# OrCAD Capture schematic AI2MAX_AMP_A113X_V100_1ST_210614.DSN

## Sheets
1 03: POWER PART1: size A3; title: 03. POWER PART 1; rev: 0.31; note: AI2 MAX-AMP B/D
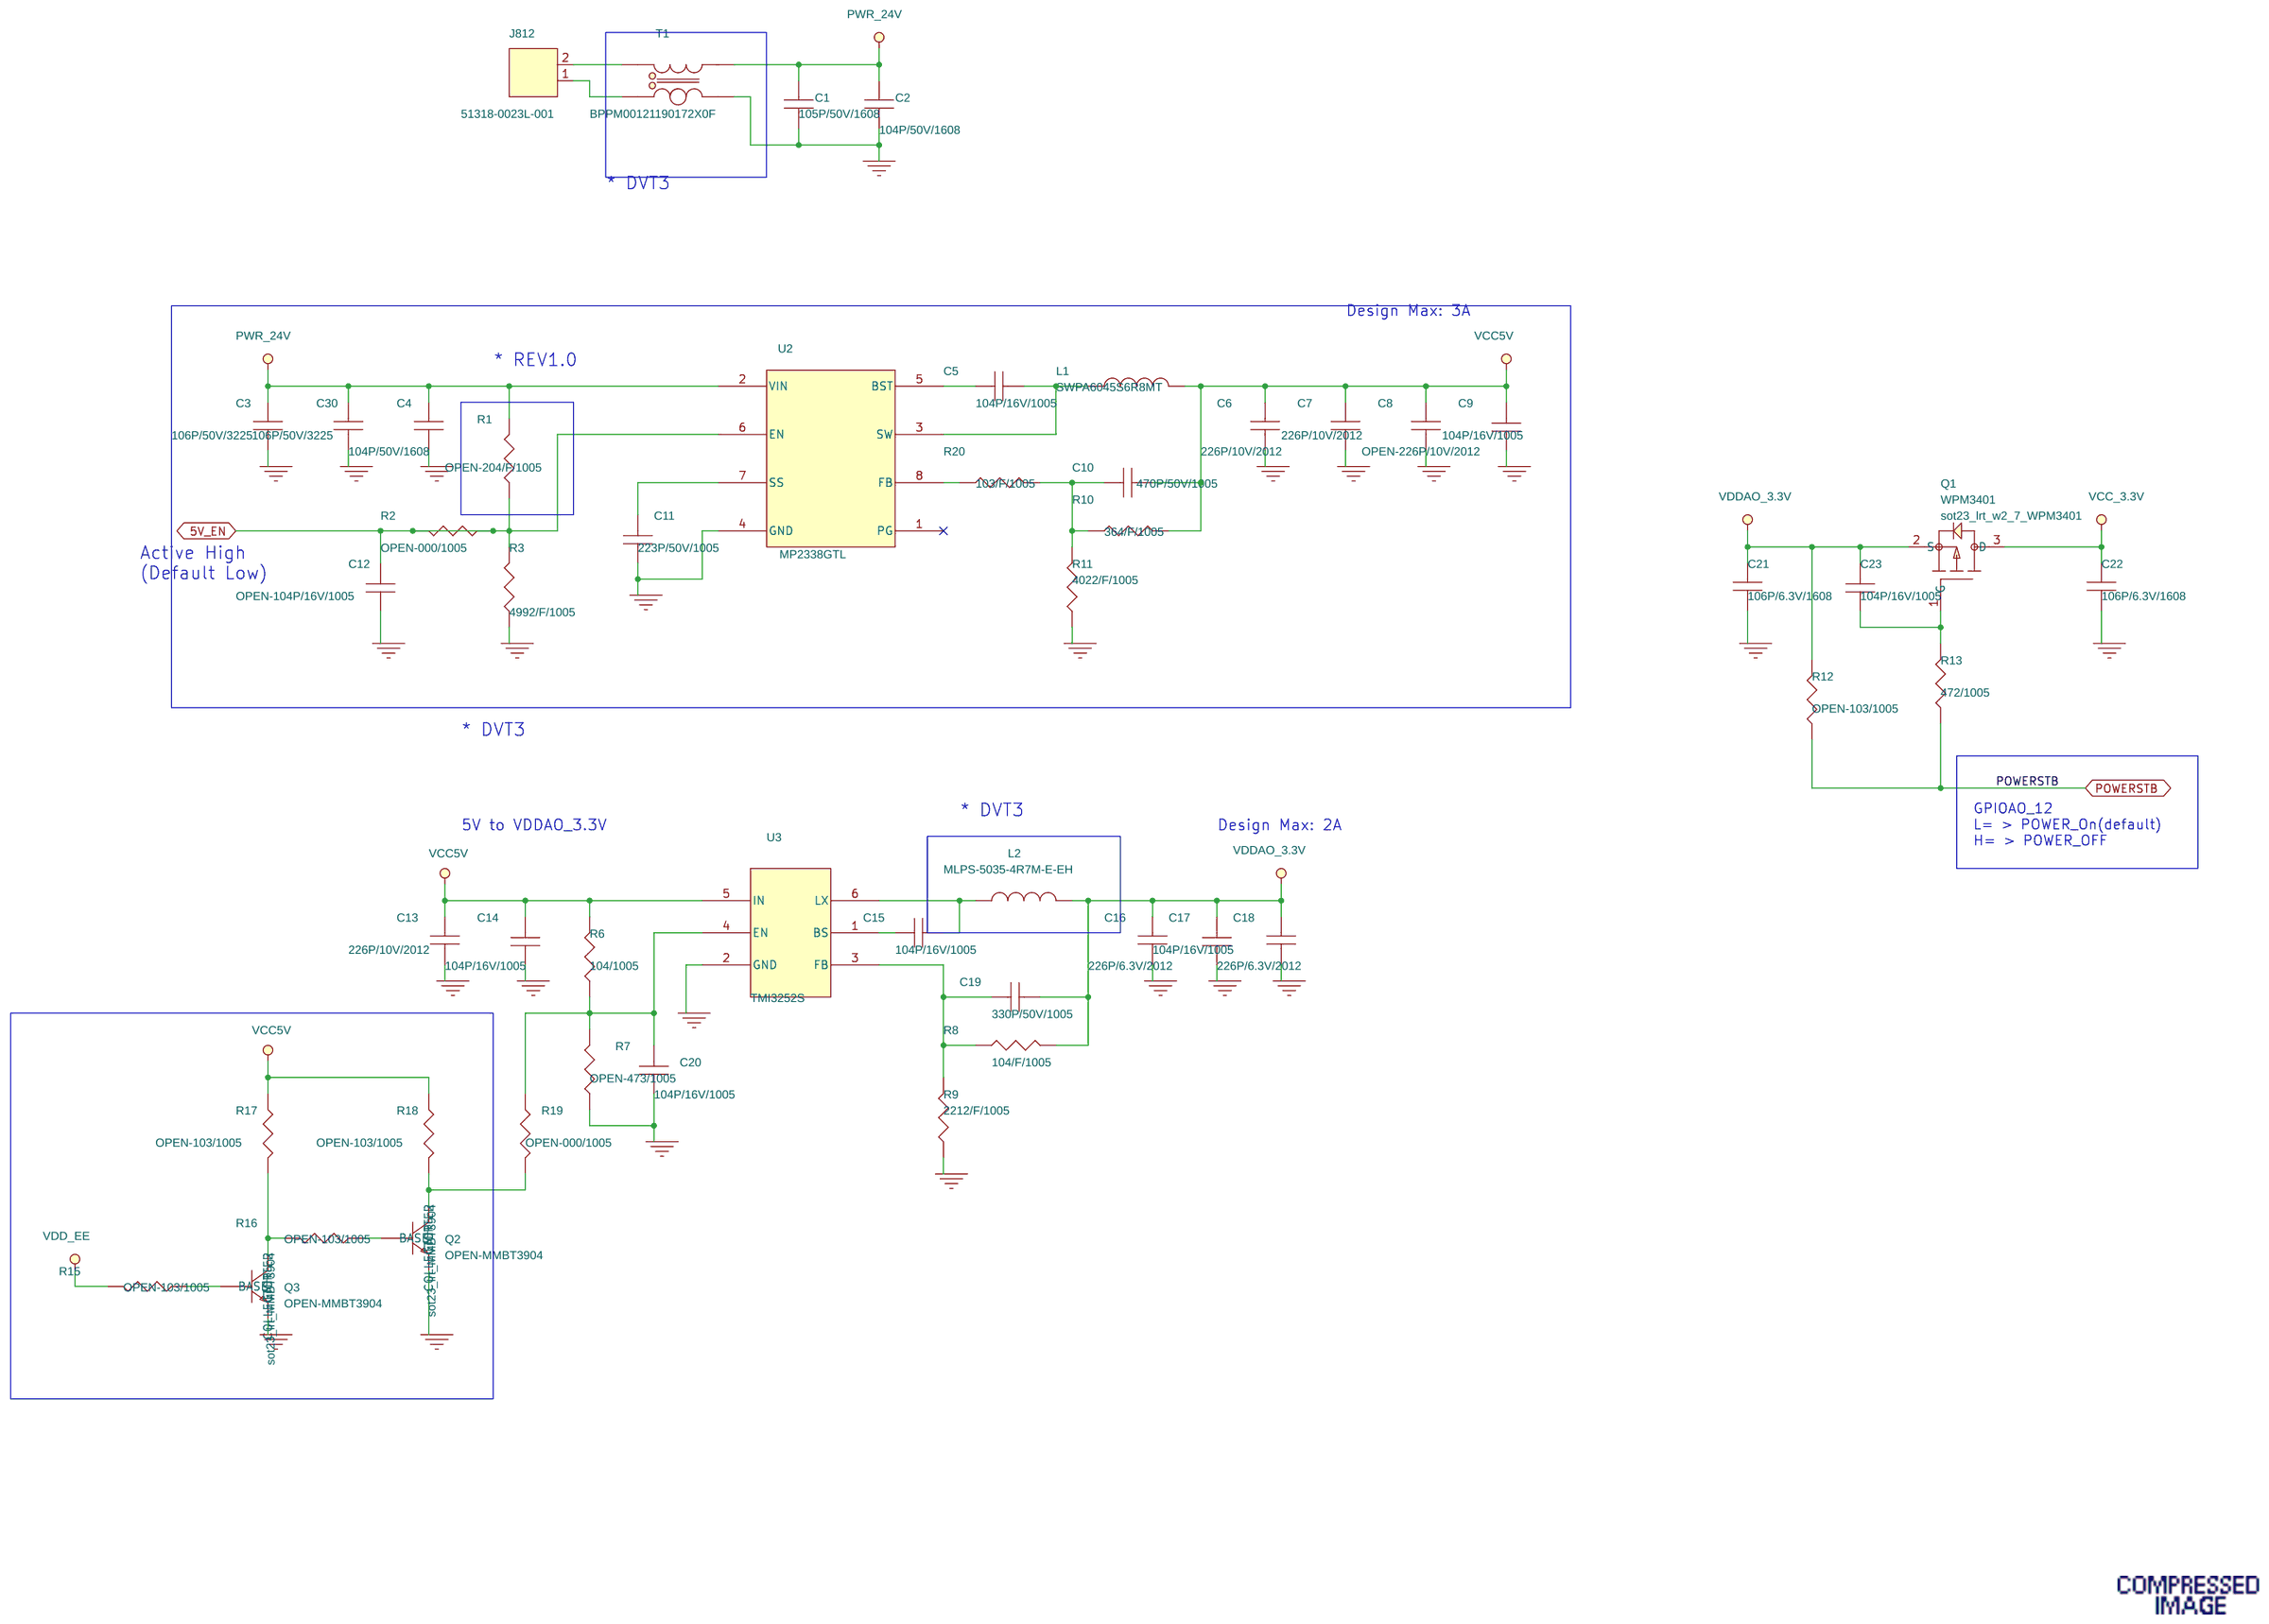
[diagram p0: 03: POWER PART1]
2 05: A113X_IO: size A3; title: 05. A113X_IO
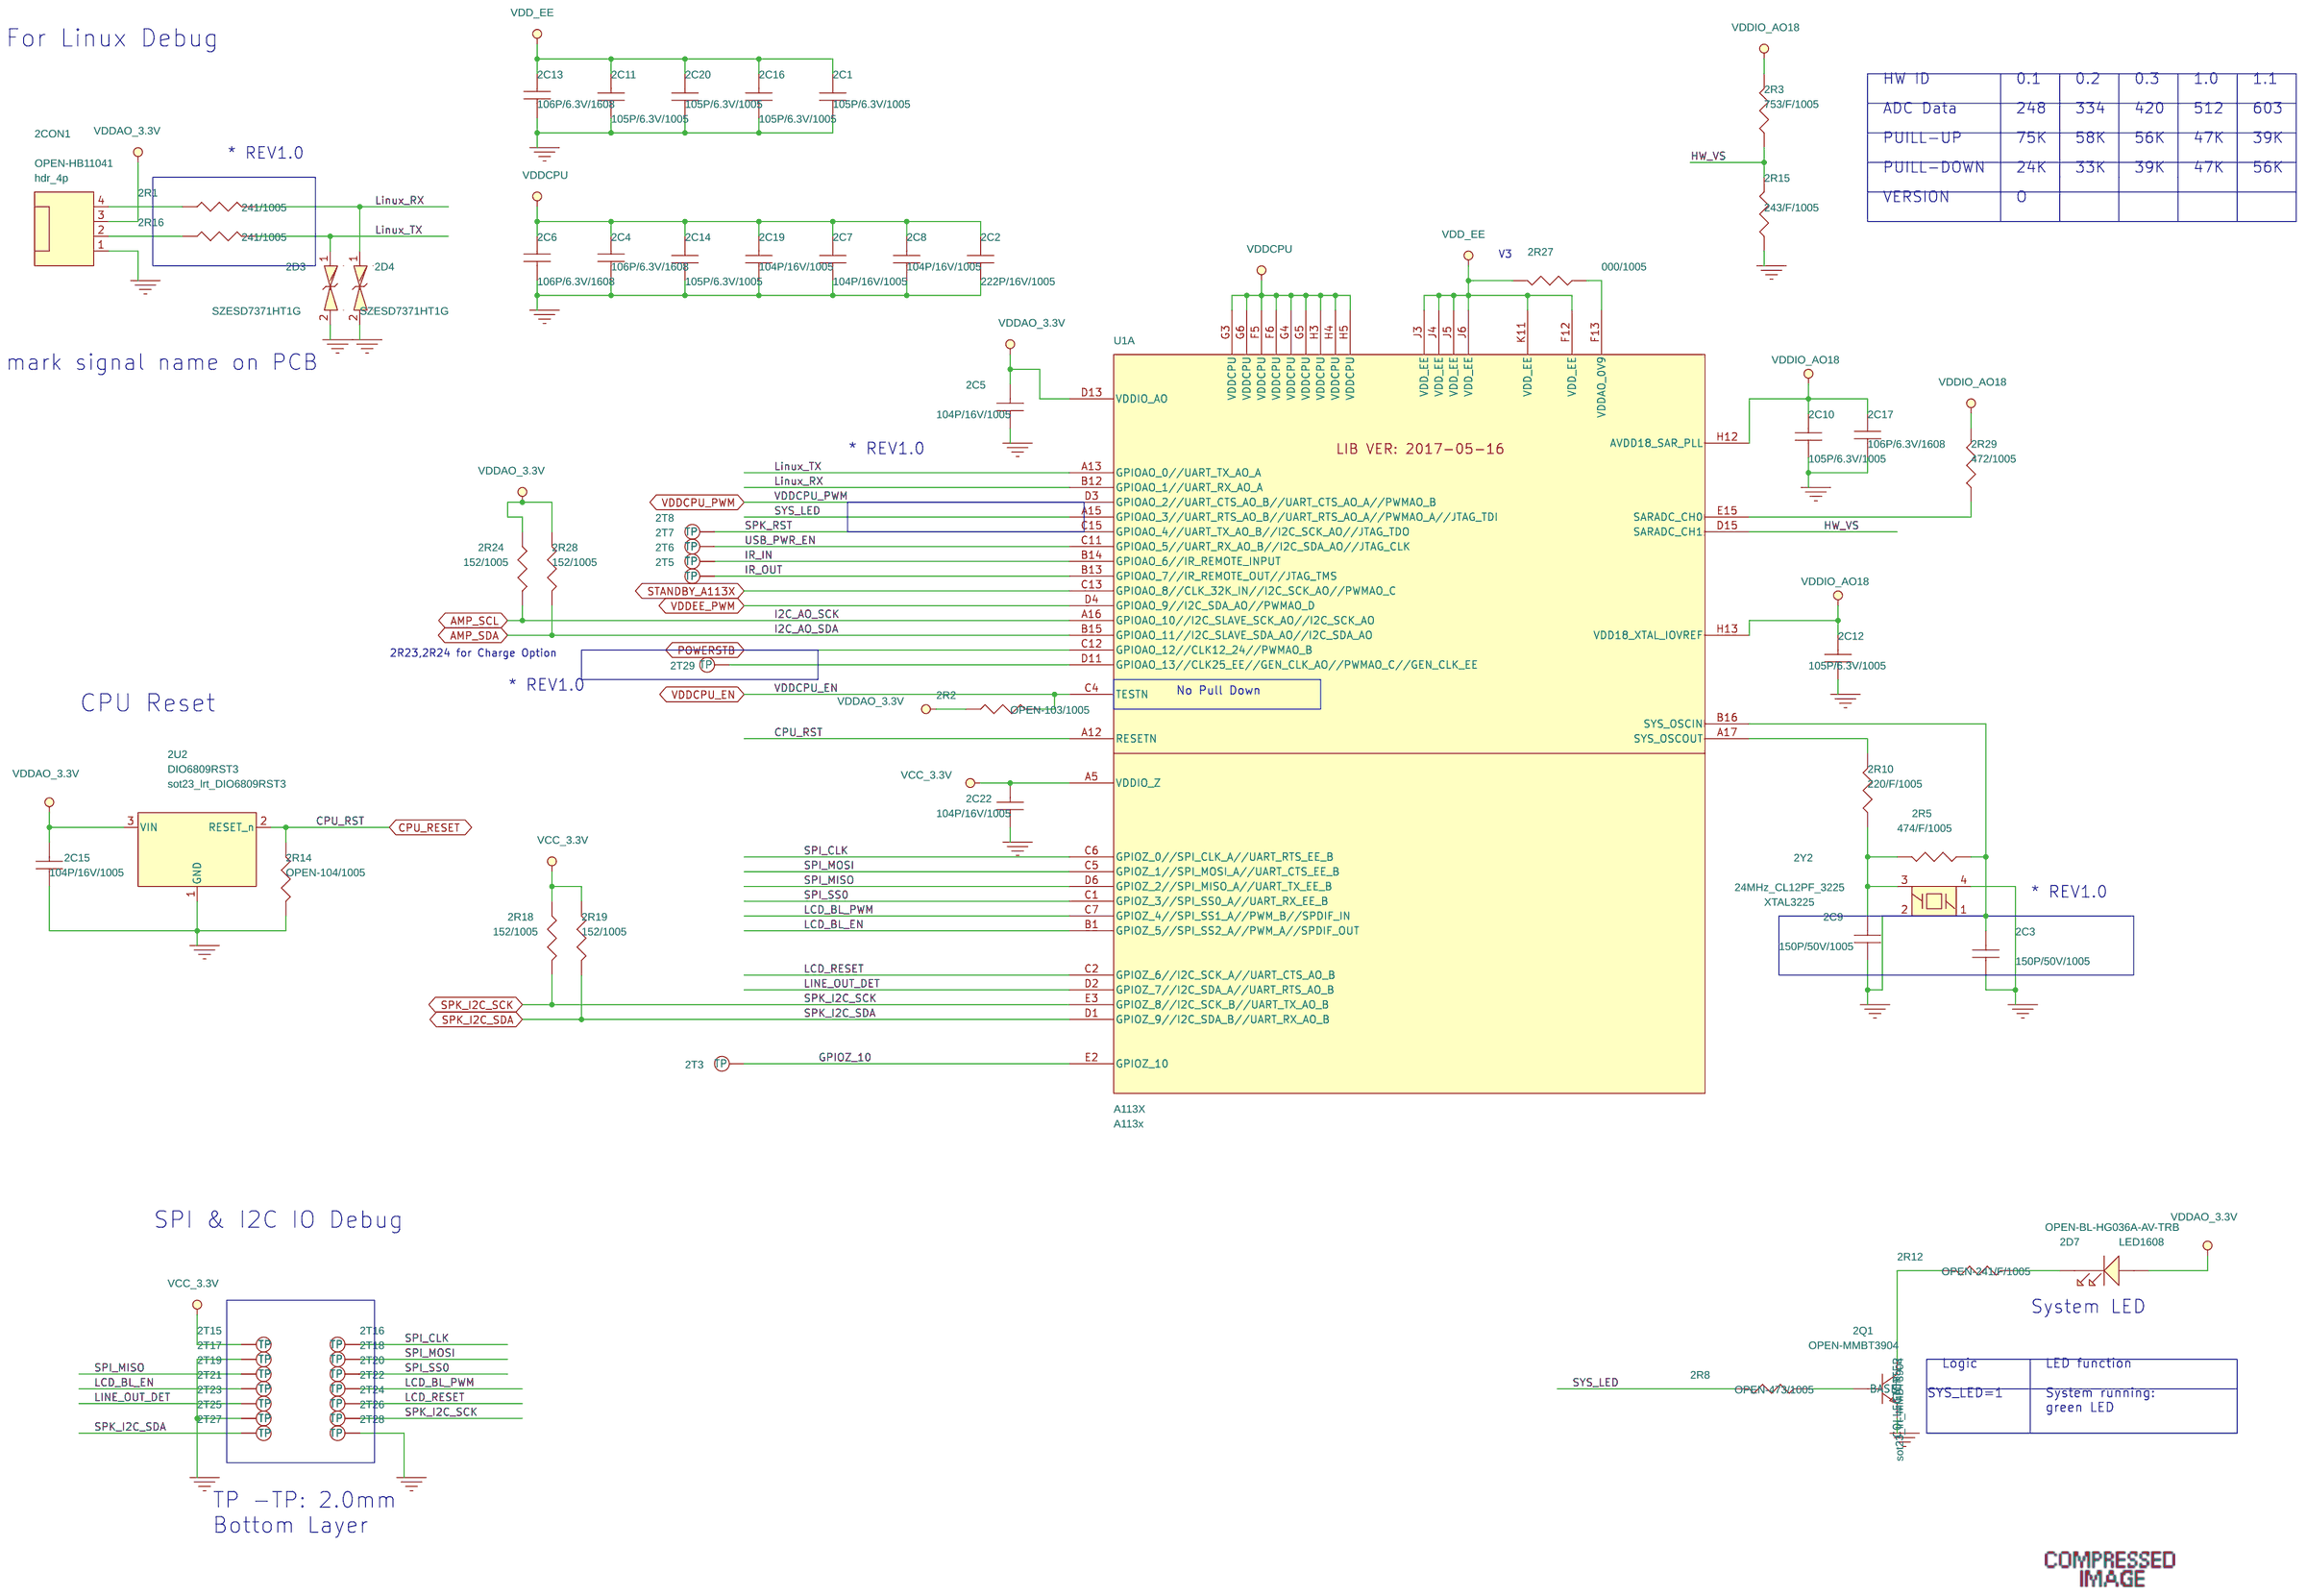
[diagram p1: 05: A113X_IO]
3 01: BLOCK: title: 01. BLOCK
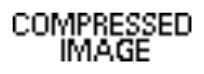
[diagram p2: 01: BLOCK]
4 02: POWER TREE: title: 02. POWER TREE
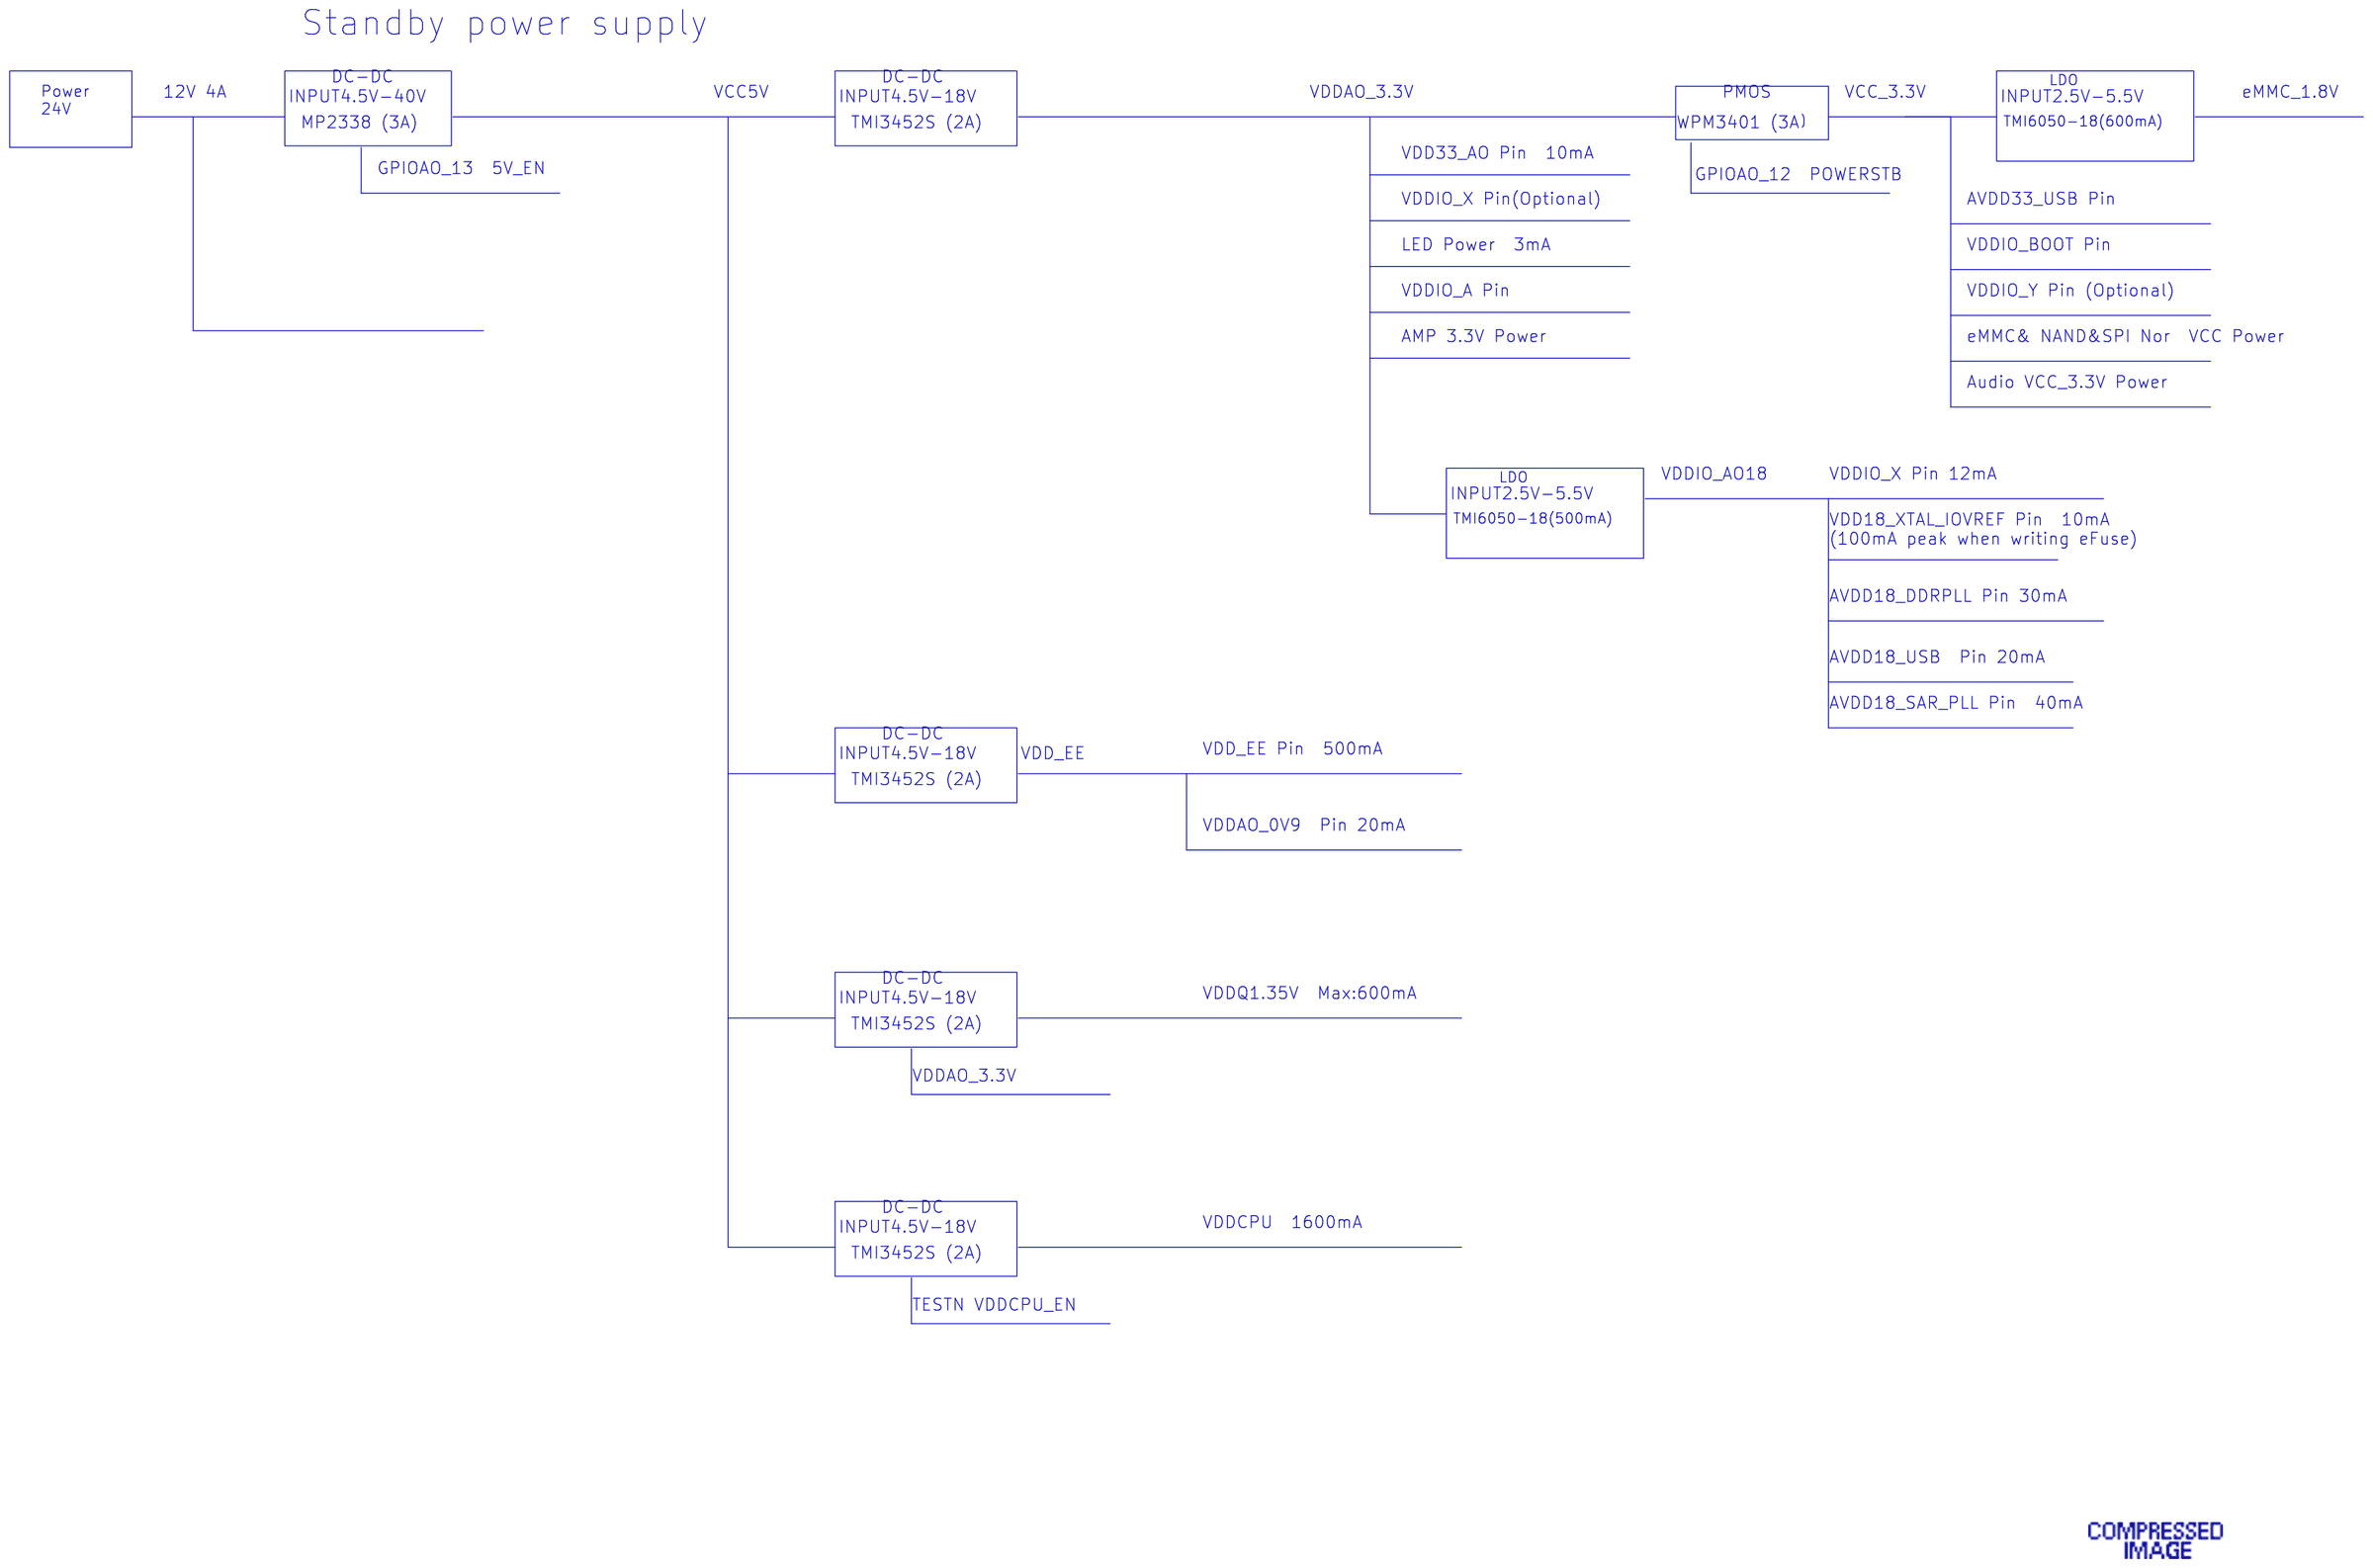
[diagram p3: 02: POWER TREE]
5 06: A113X_DDR3L: size A3; title: 06. A113X_DDR
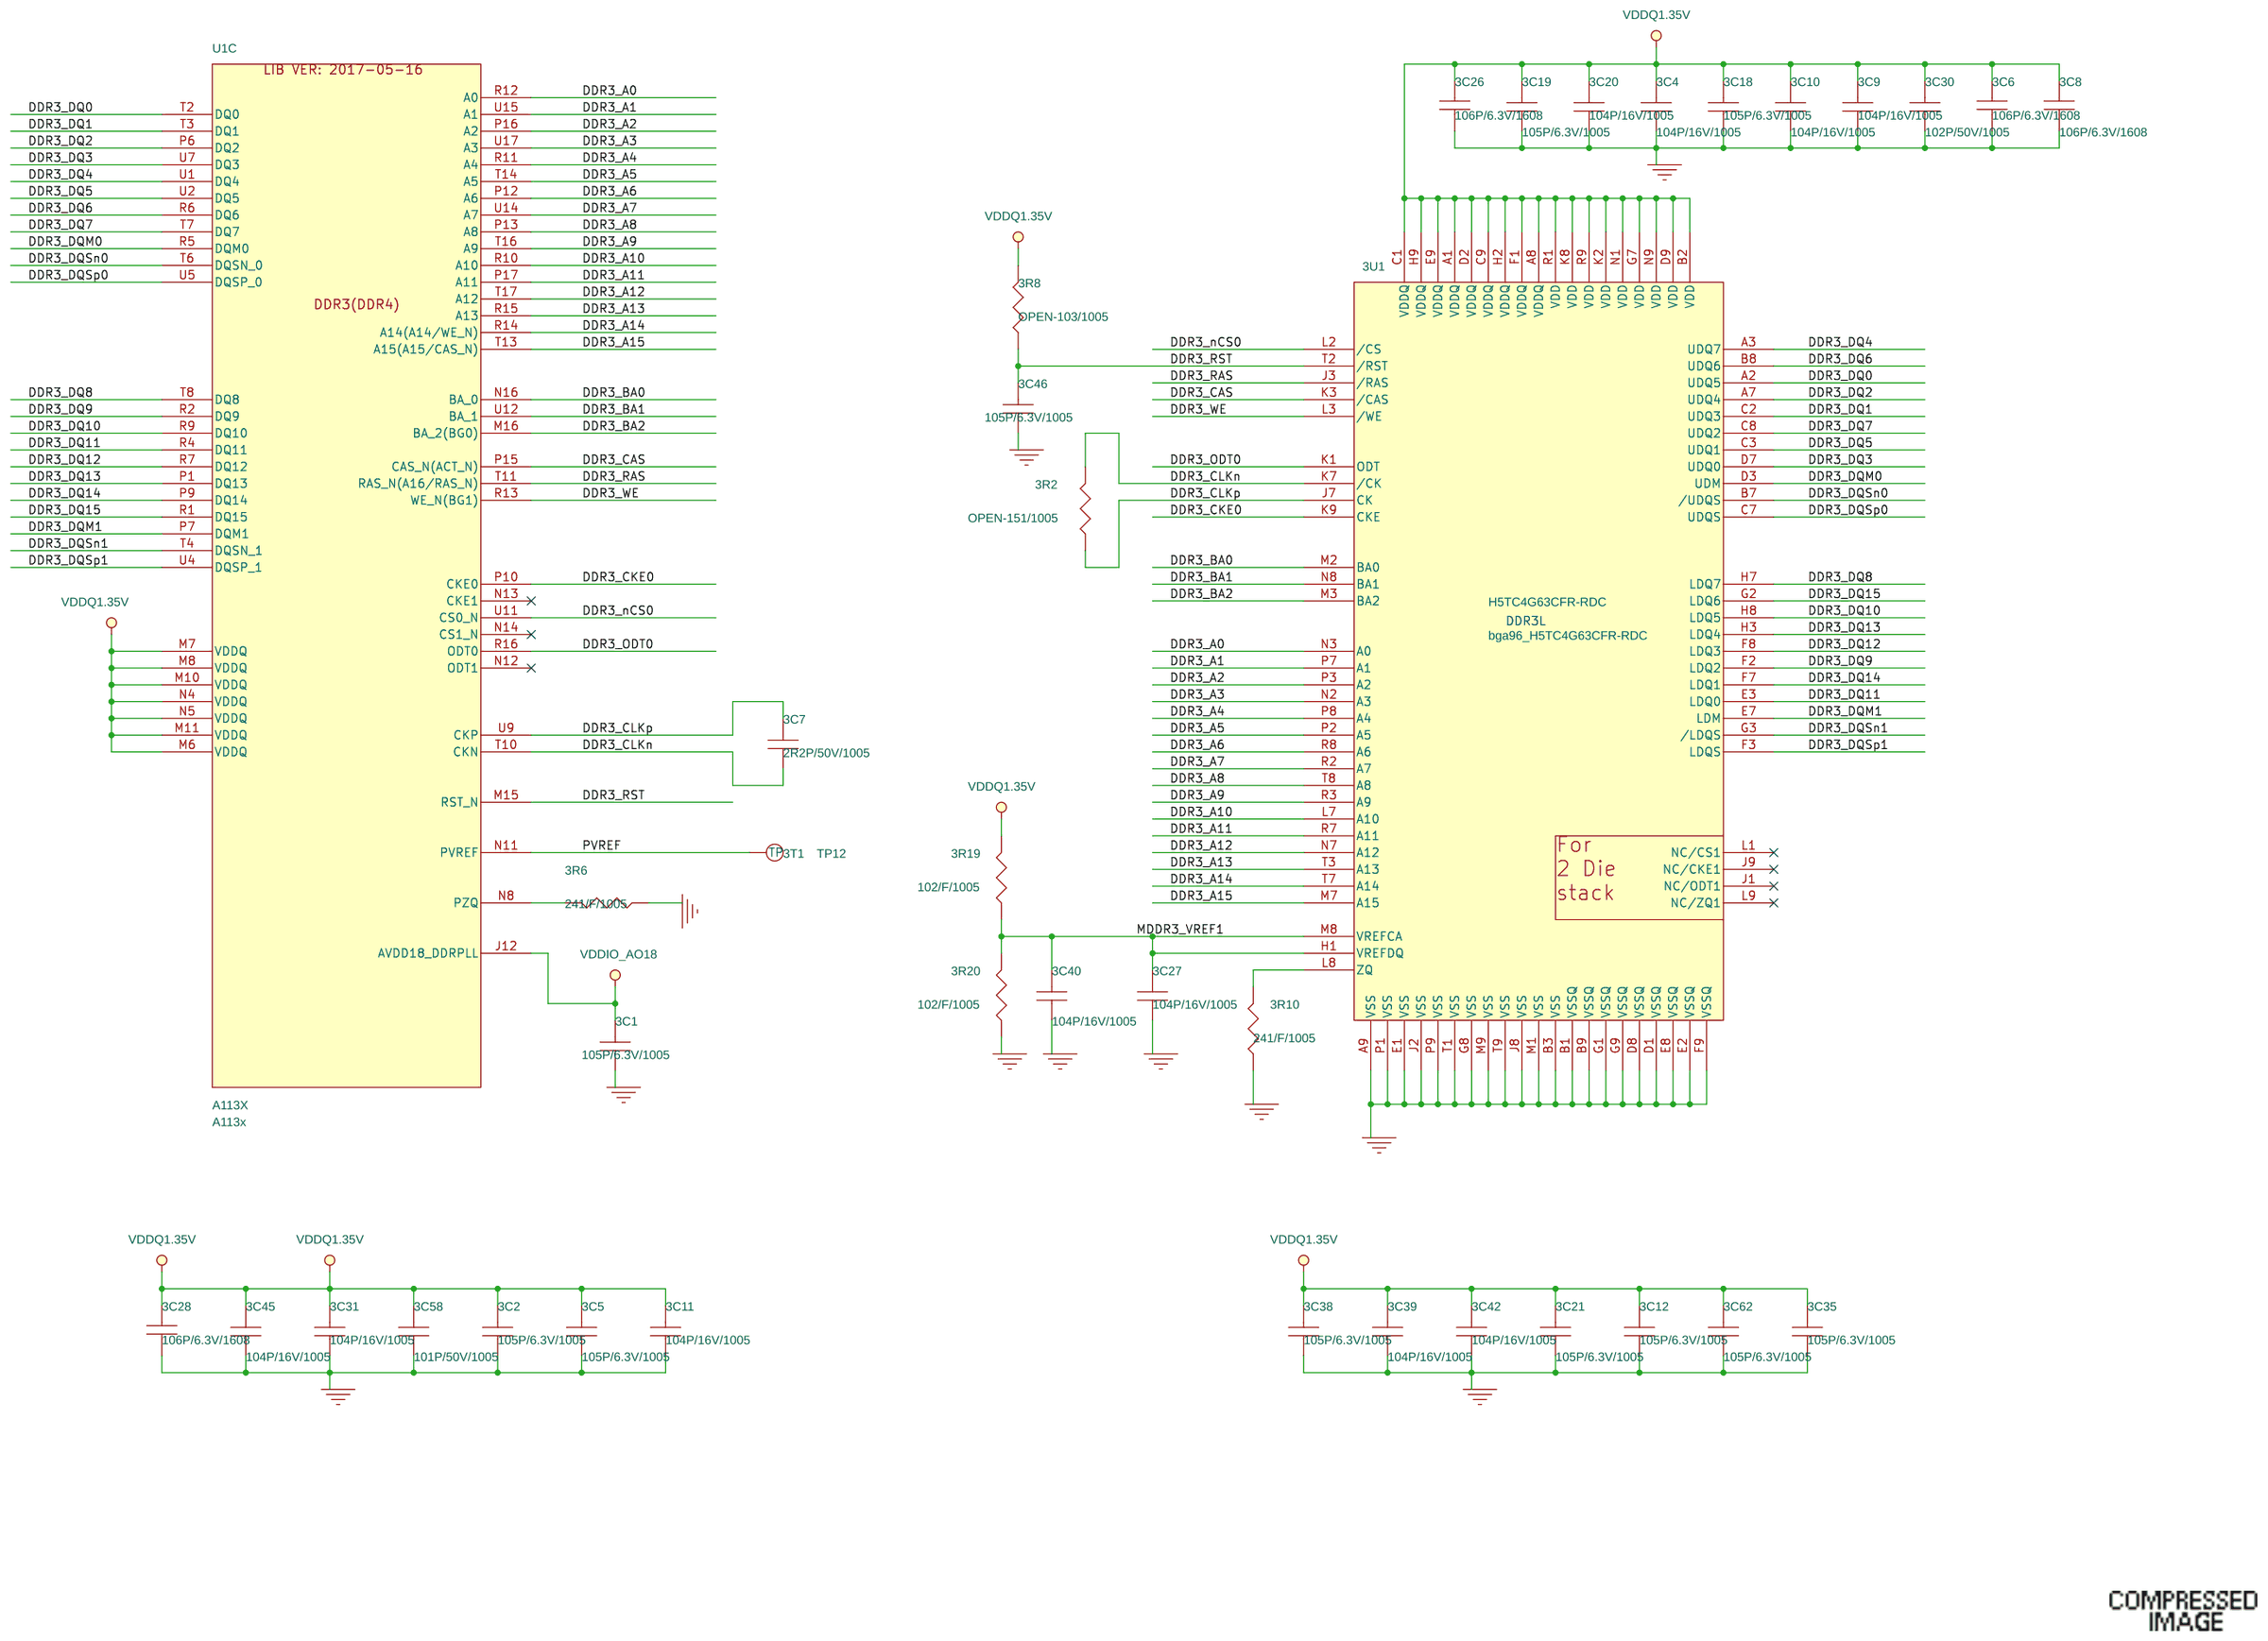
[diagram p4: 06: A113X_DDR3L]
6 04: POWER PART2: size A3; title: 04. POWER PART2; rev: 0.1
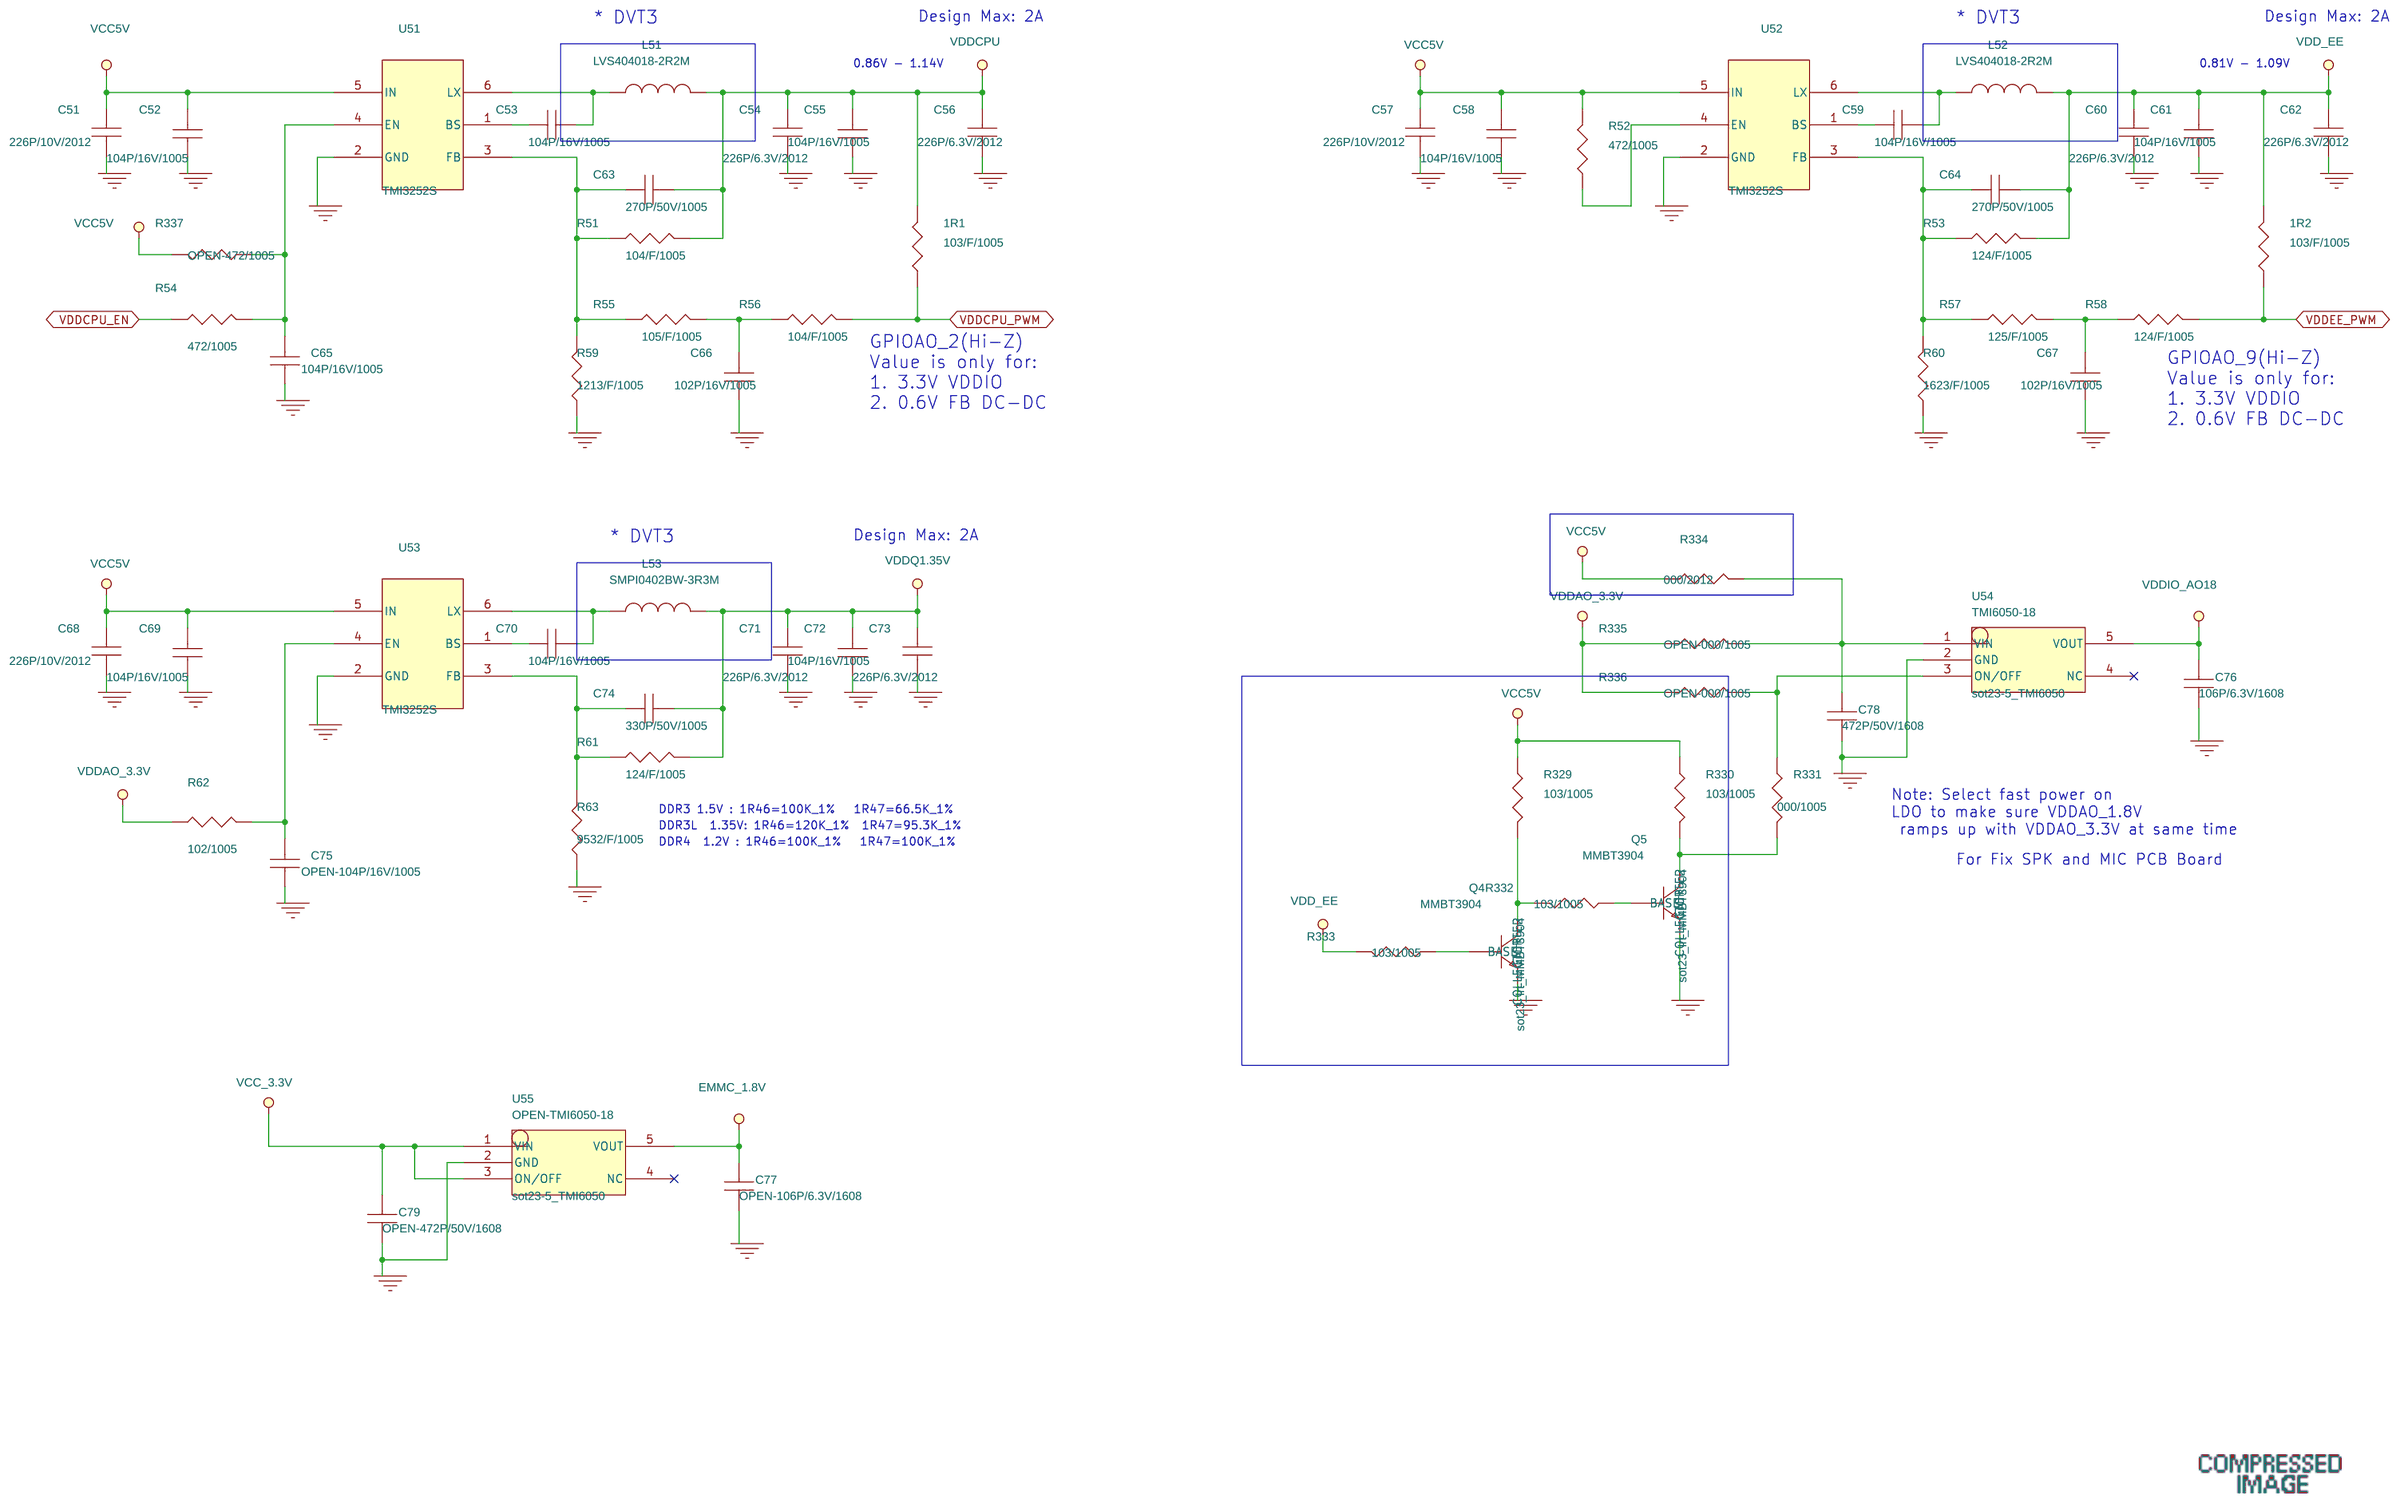
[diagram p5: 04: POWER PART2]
7 08: A113X_POWER: size A3; title: 08. A113X_POWER
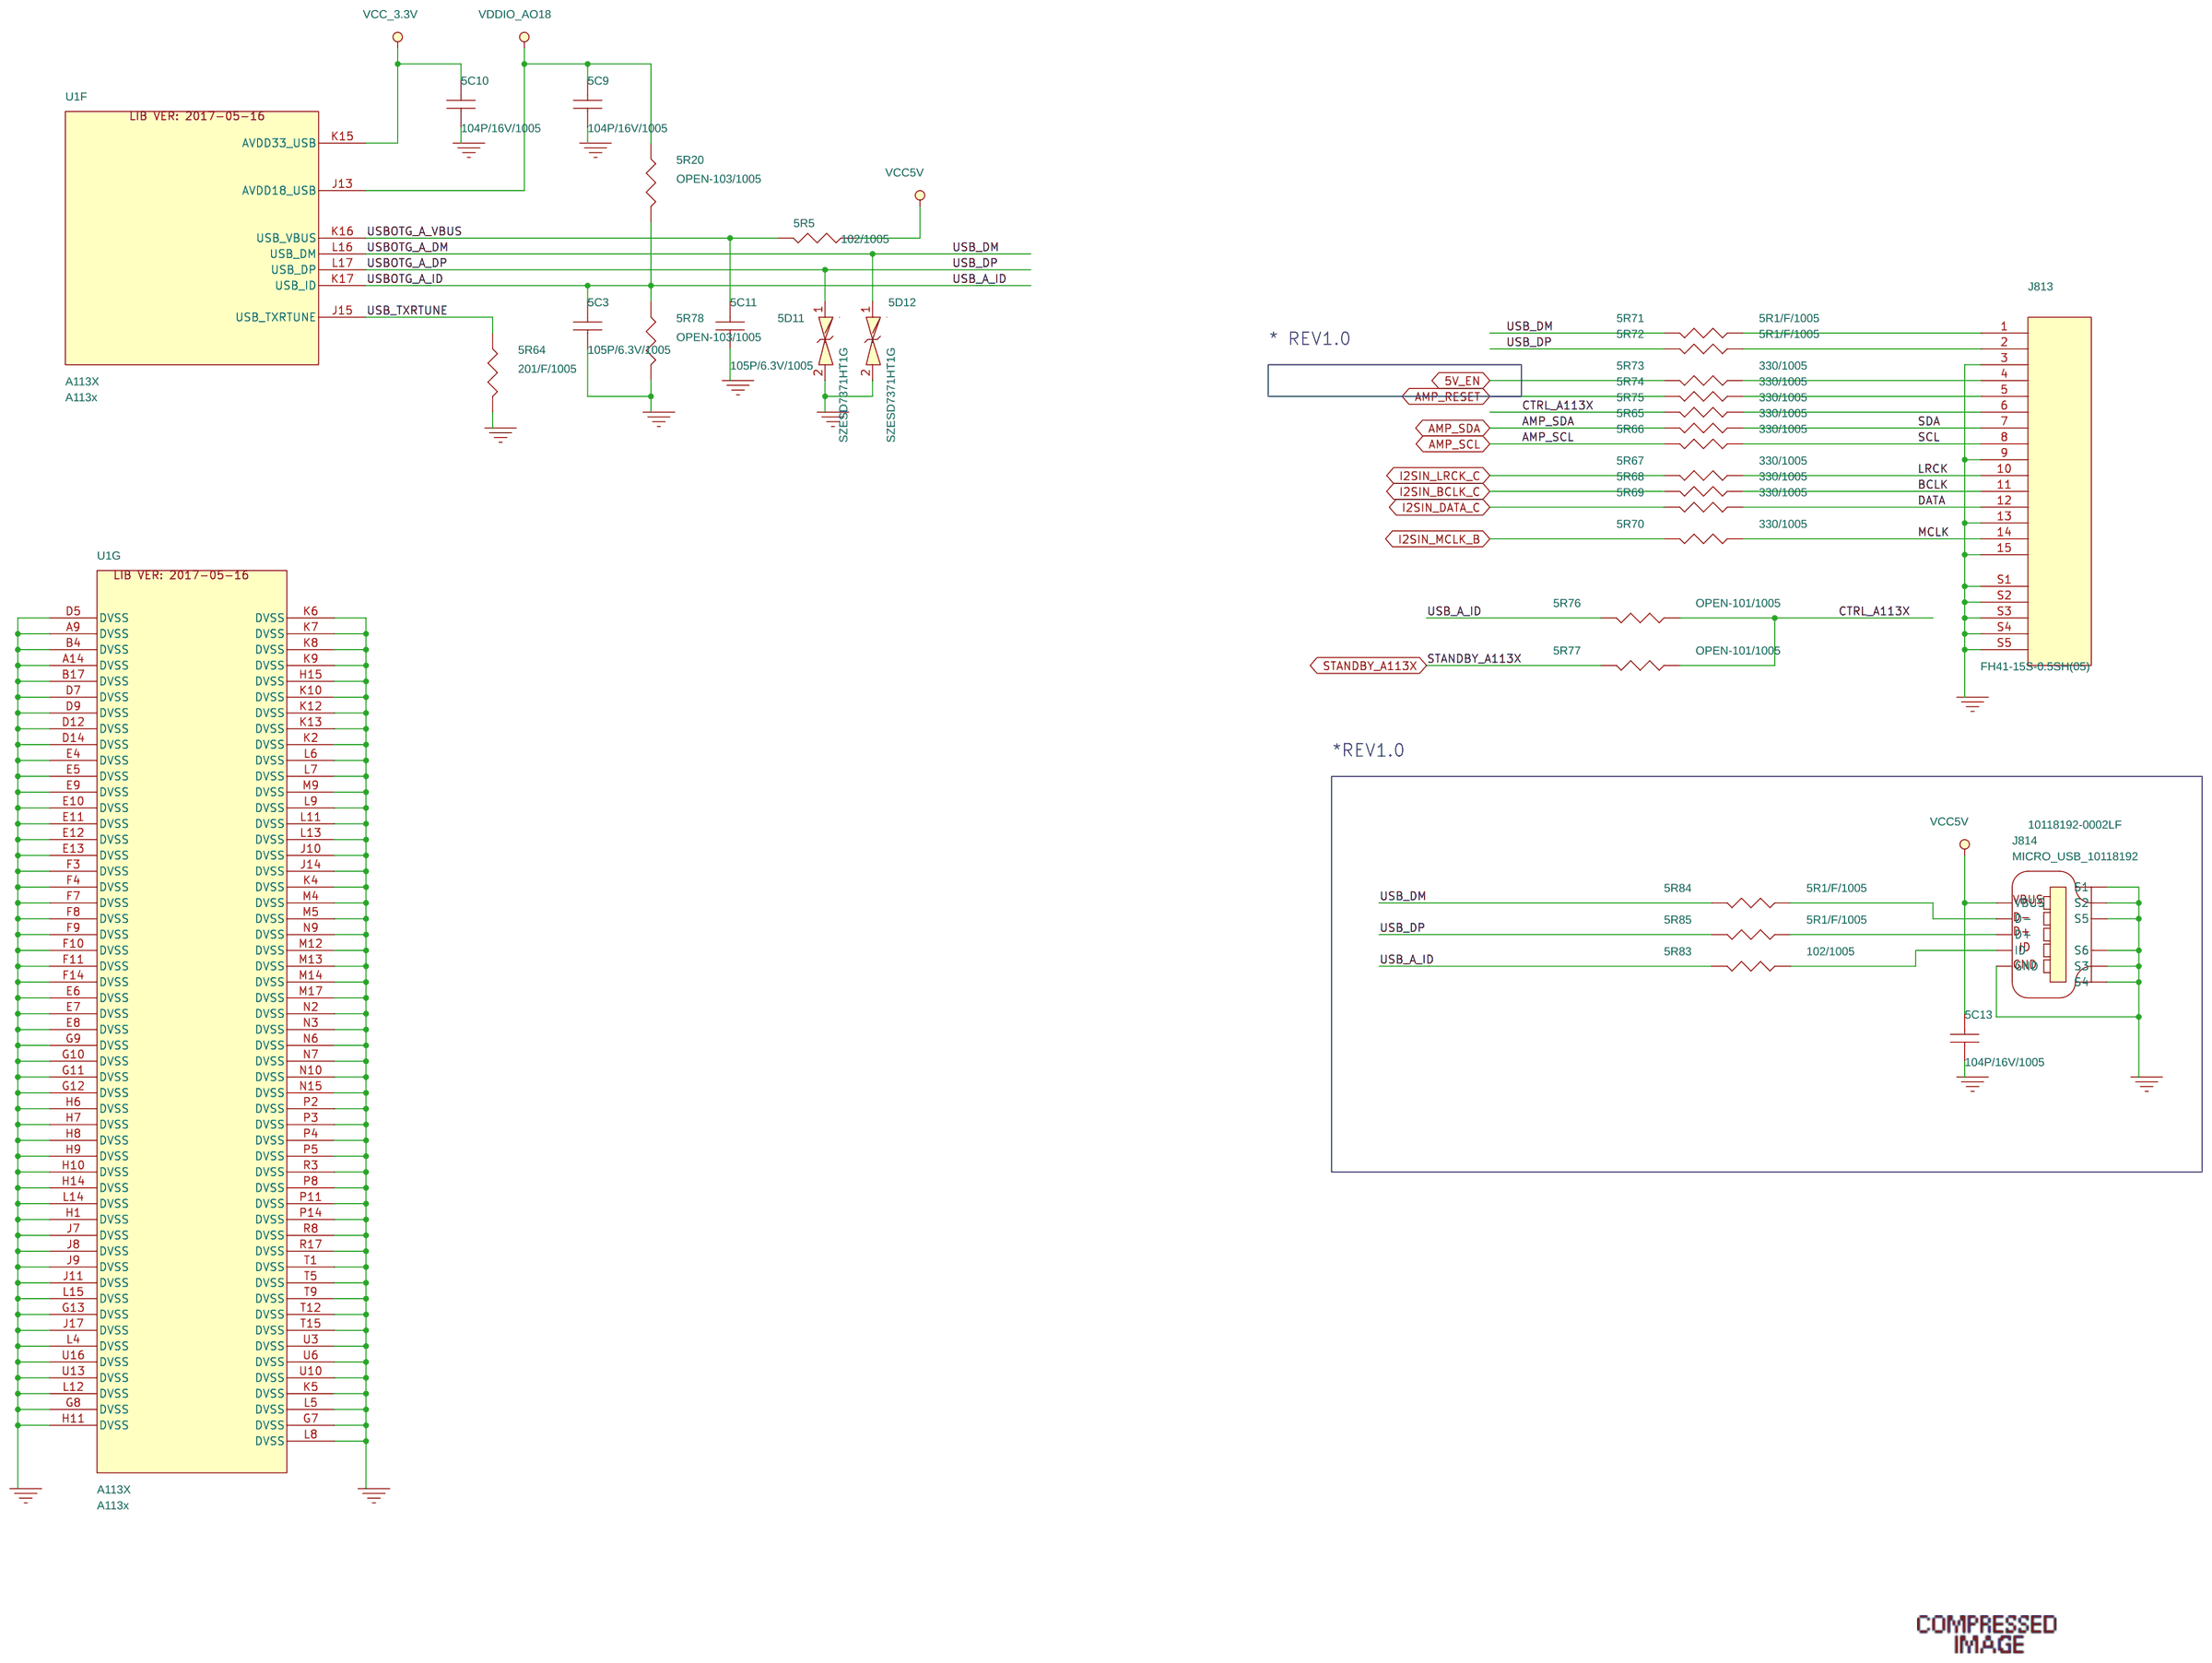
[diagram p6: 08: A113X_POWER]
8 07: A113X_FLASH: size A3; title: 07. A113X_FLASH
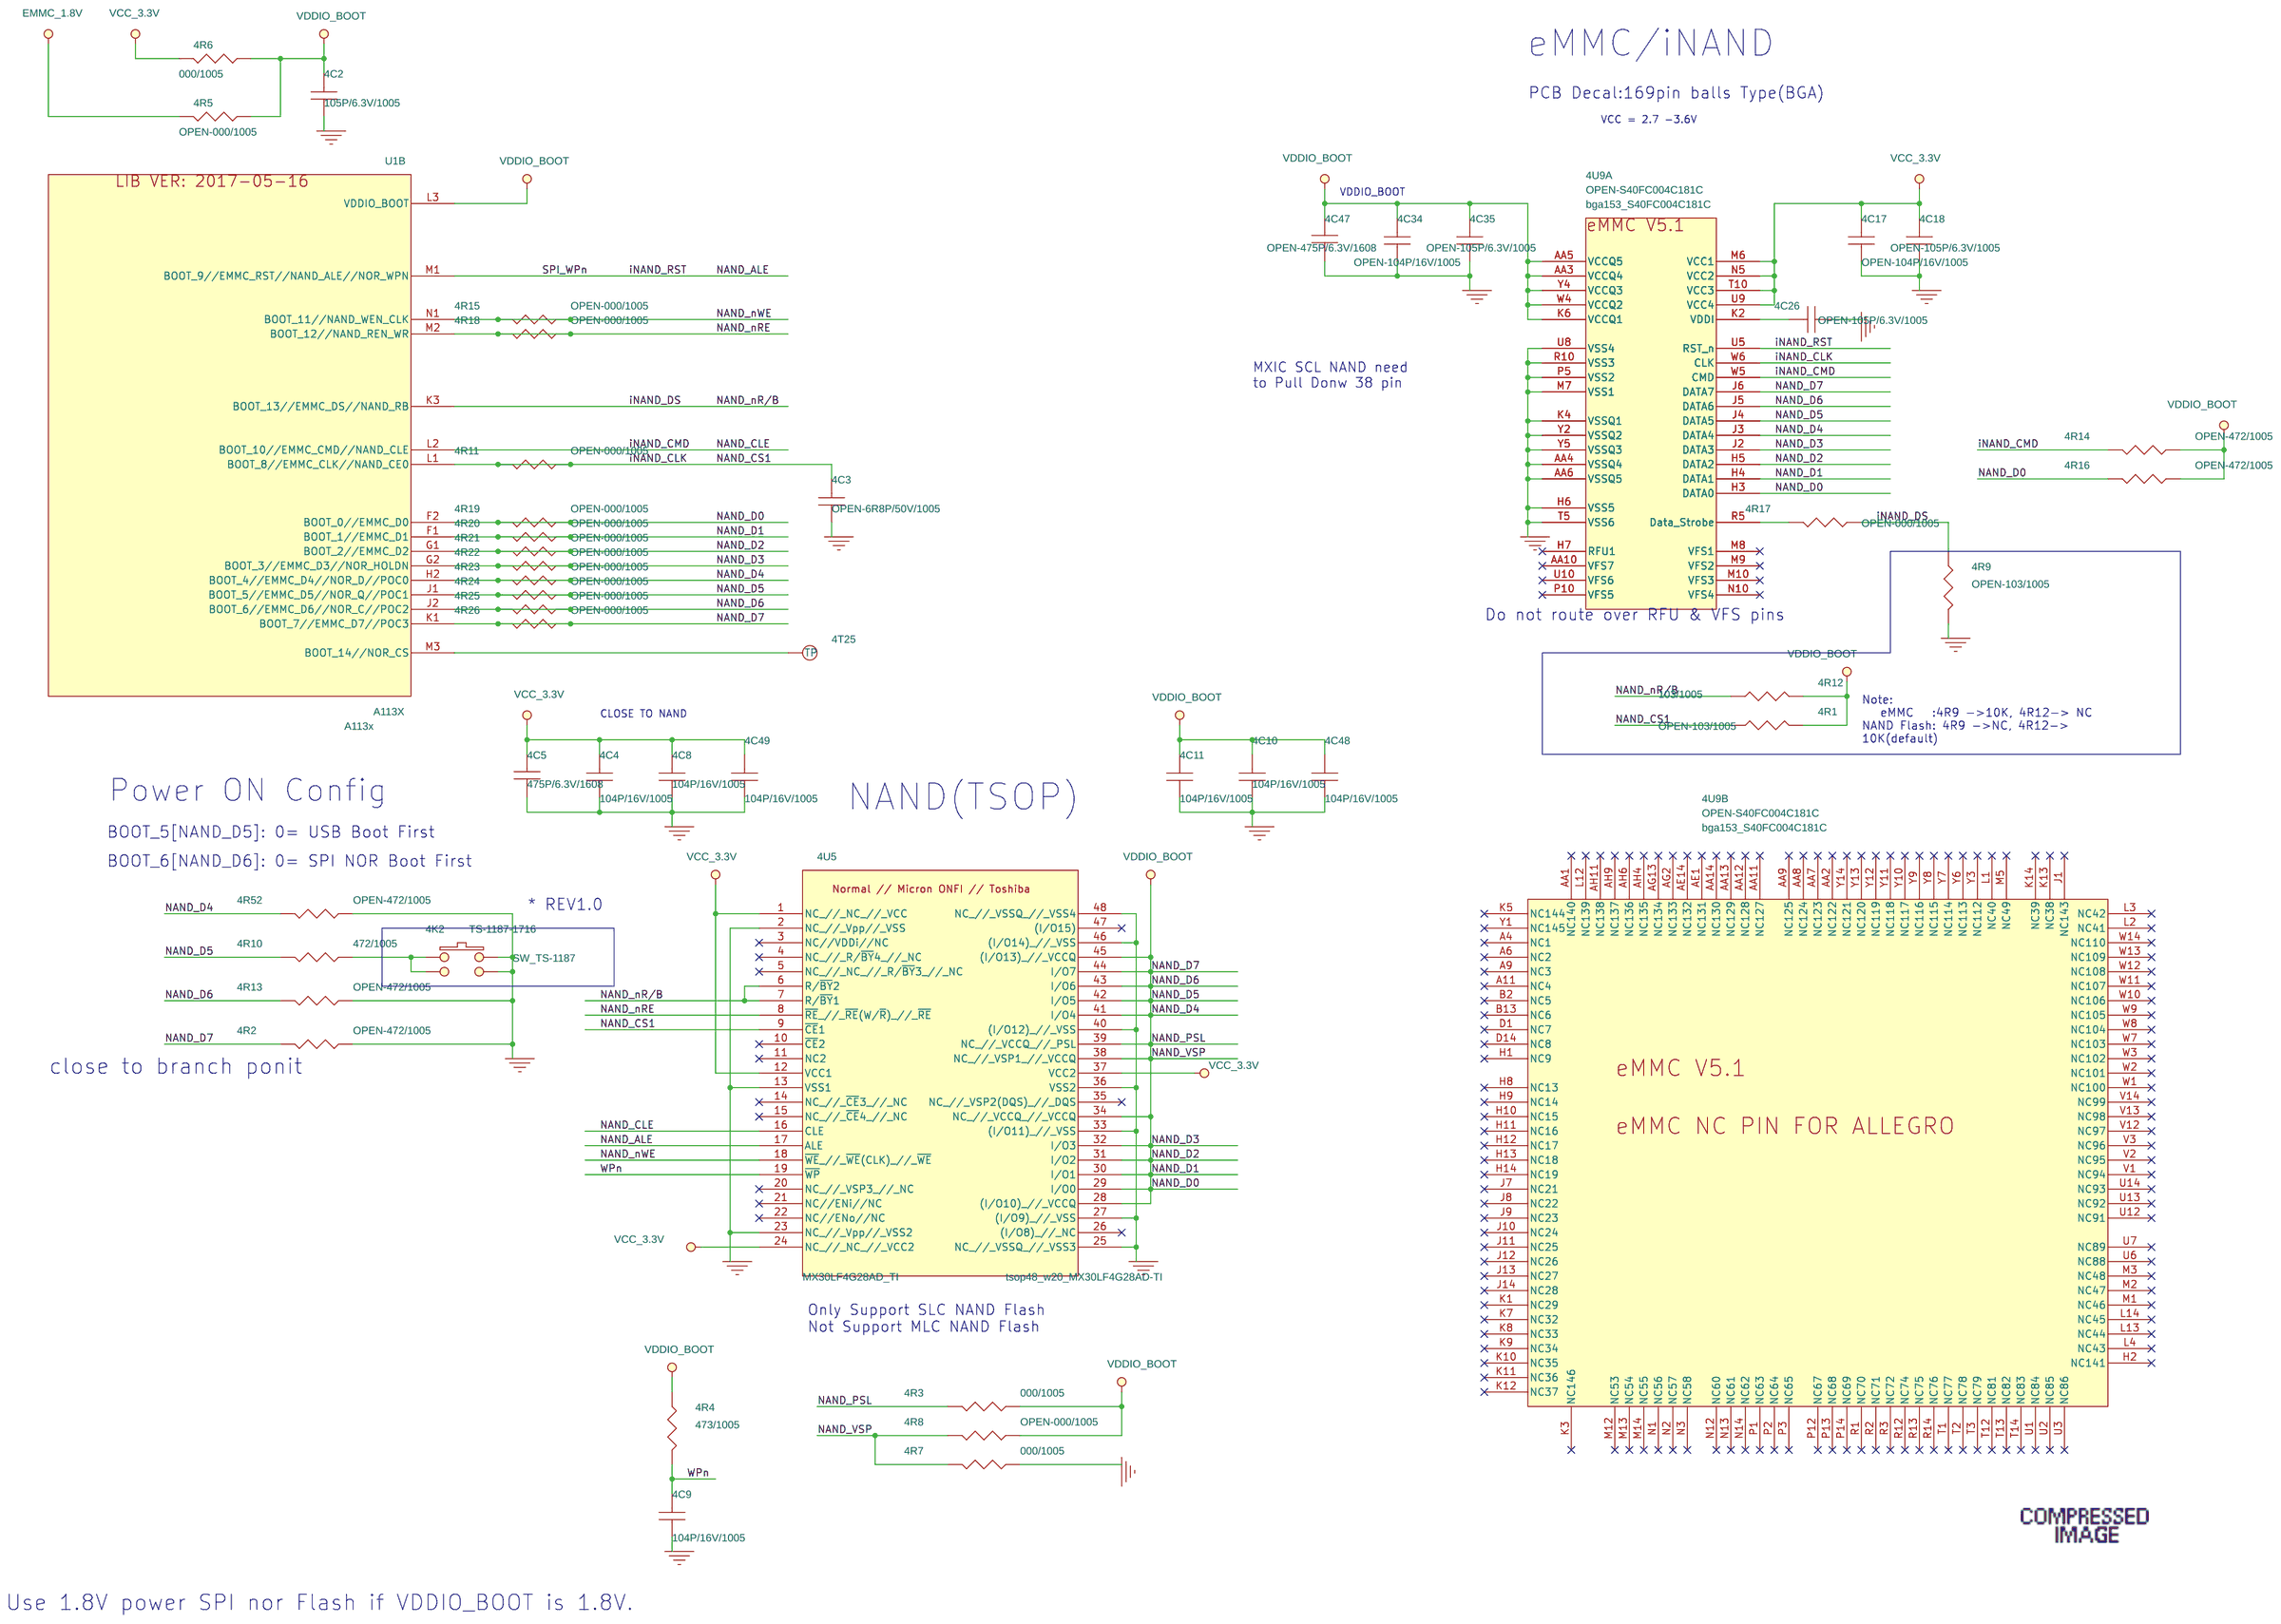
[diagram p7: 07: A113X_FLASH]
9 11: AUDIO AMP RIGHT: size A3; title: 11. AUDIO AMP_RIGHT
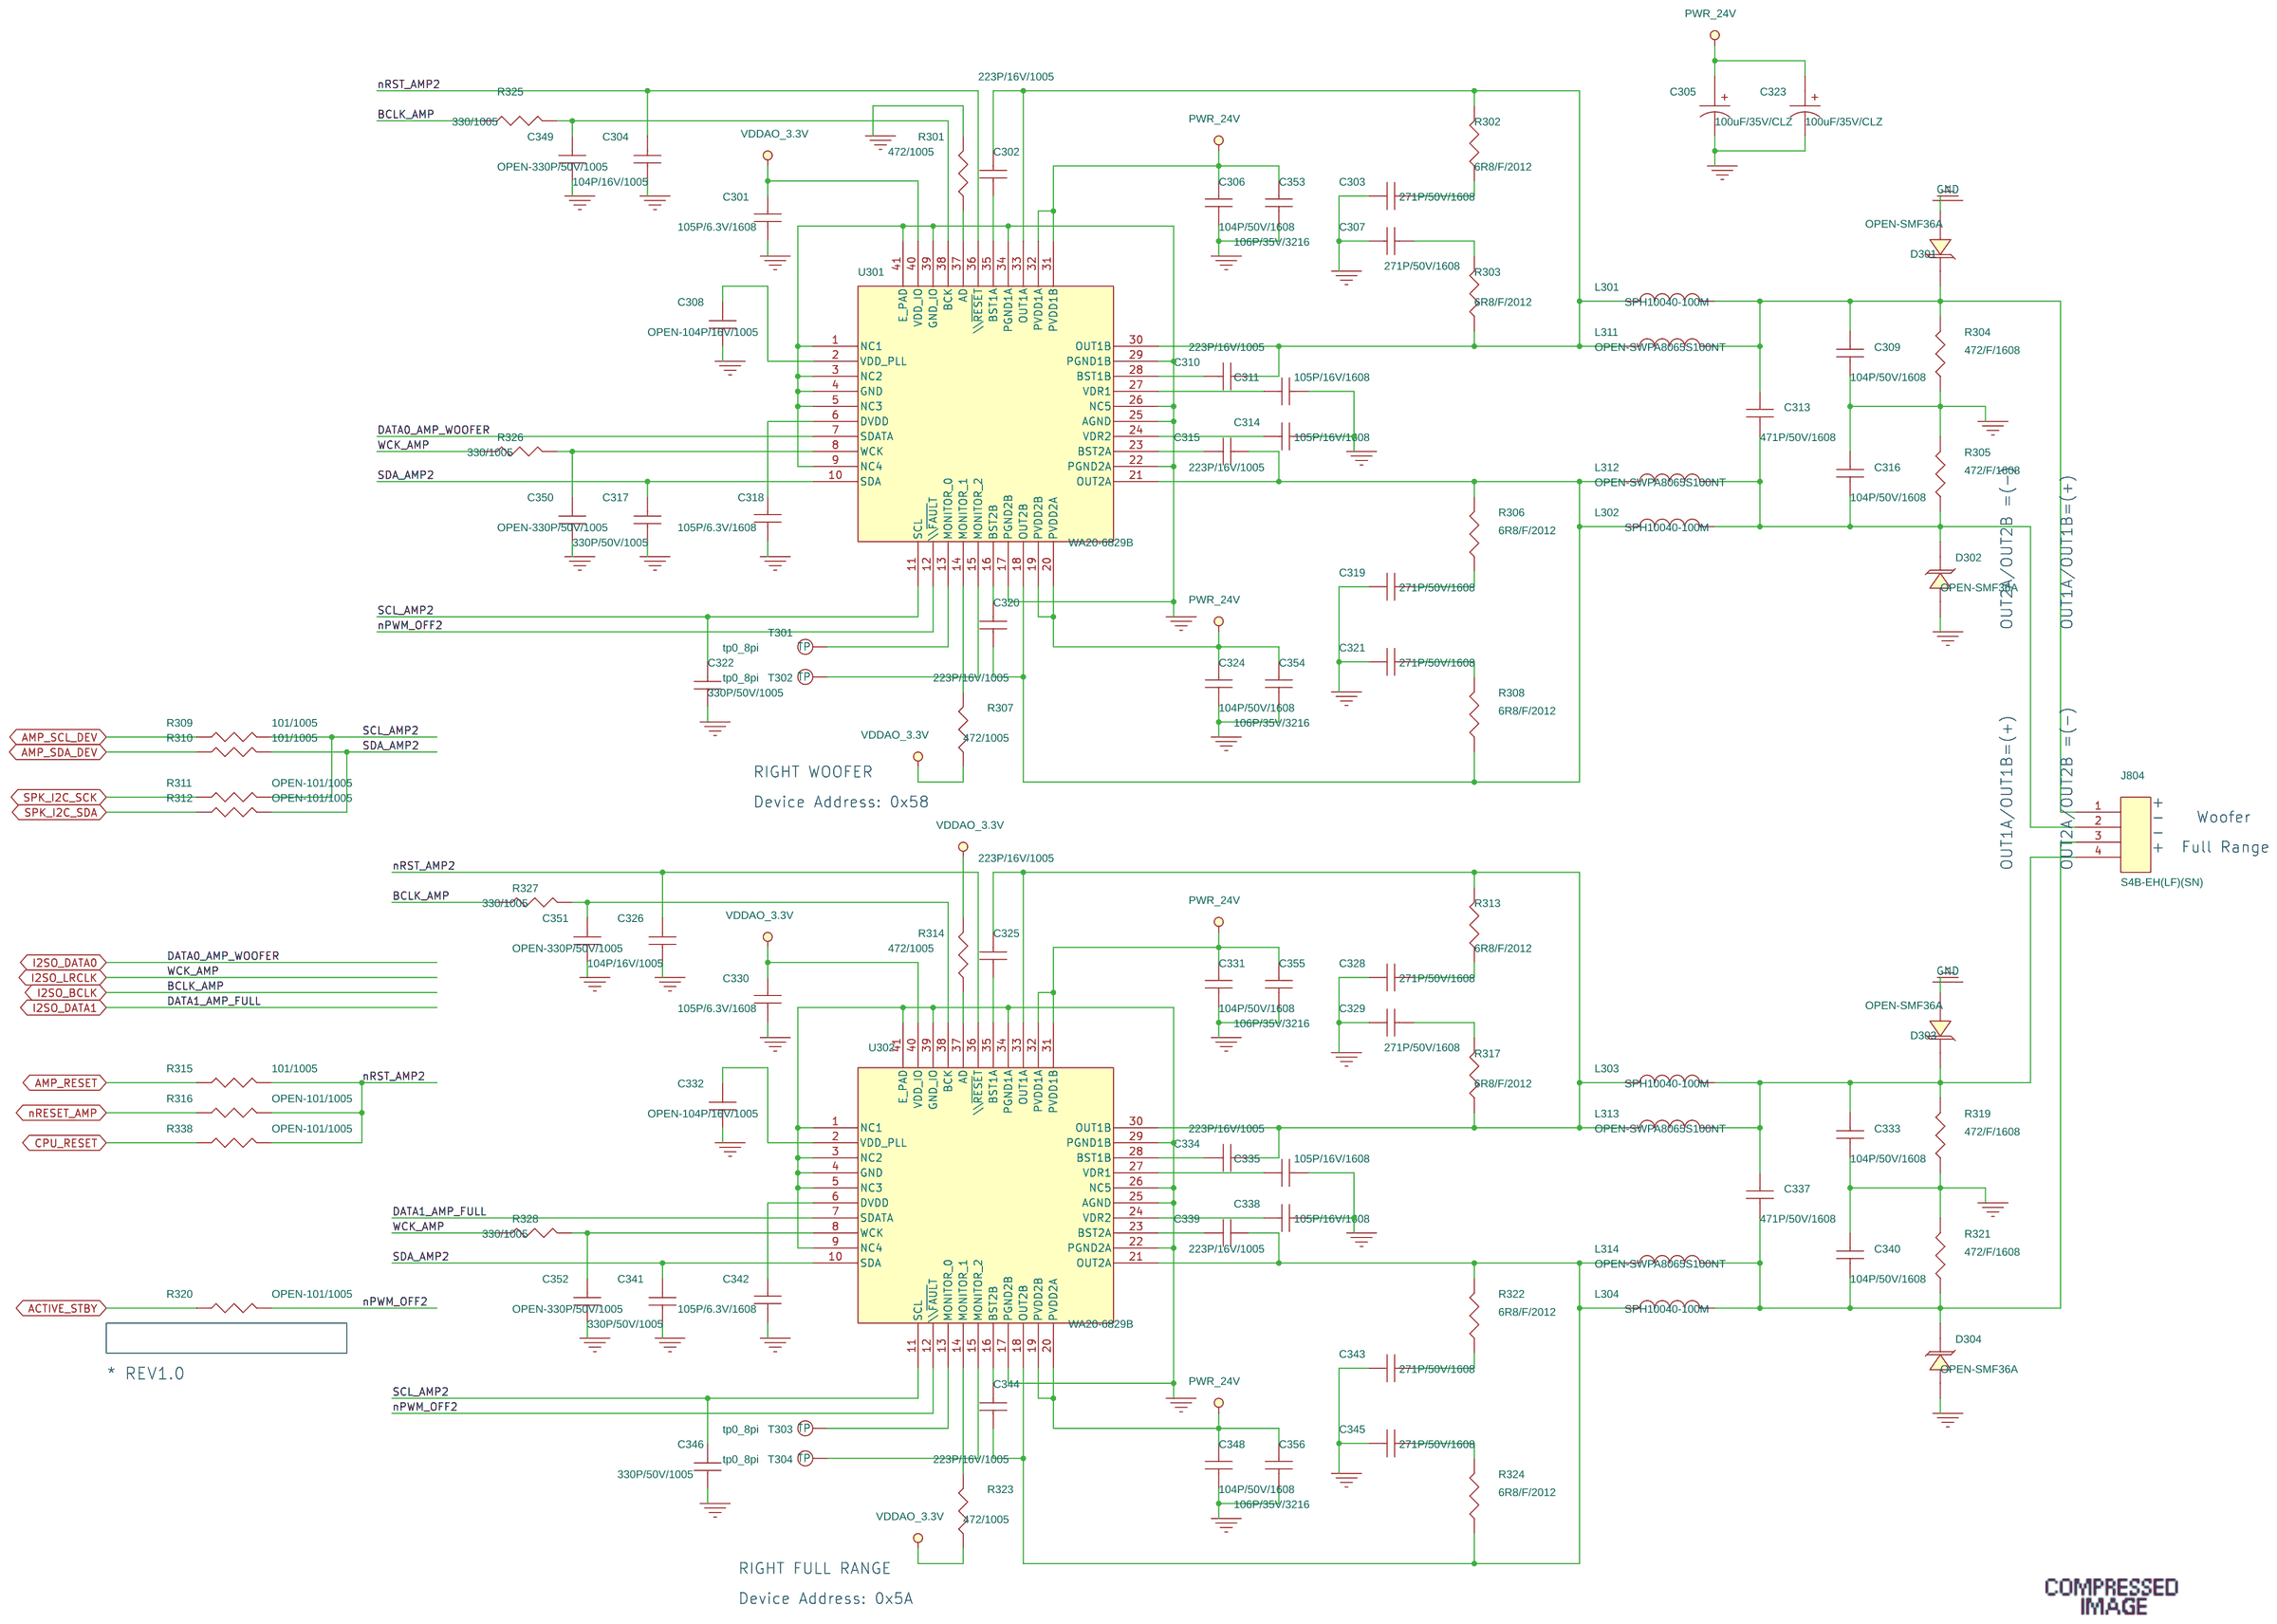
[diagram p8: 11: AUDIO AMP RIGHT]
10 10: AUDIO AMP LEFT: size A3; title: 10. AUDIO AMP_LEFT
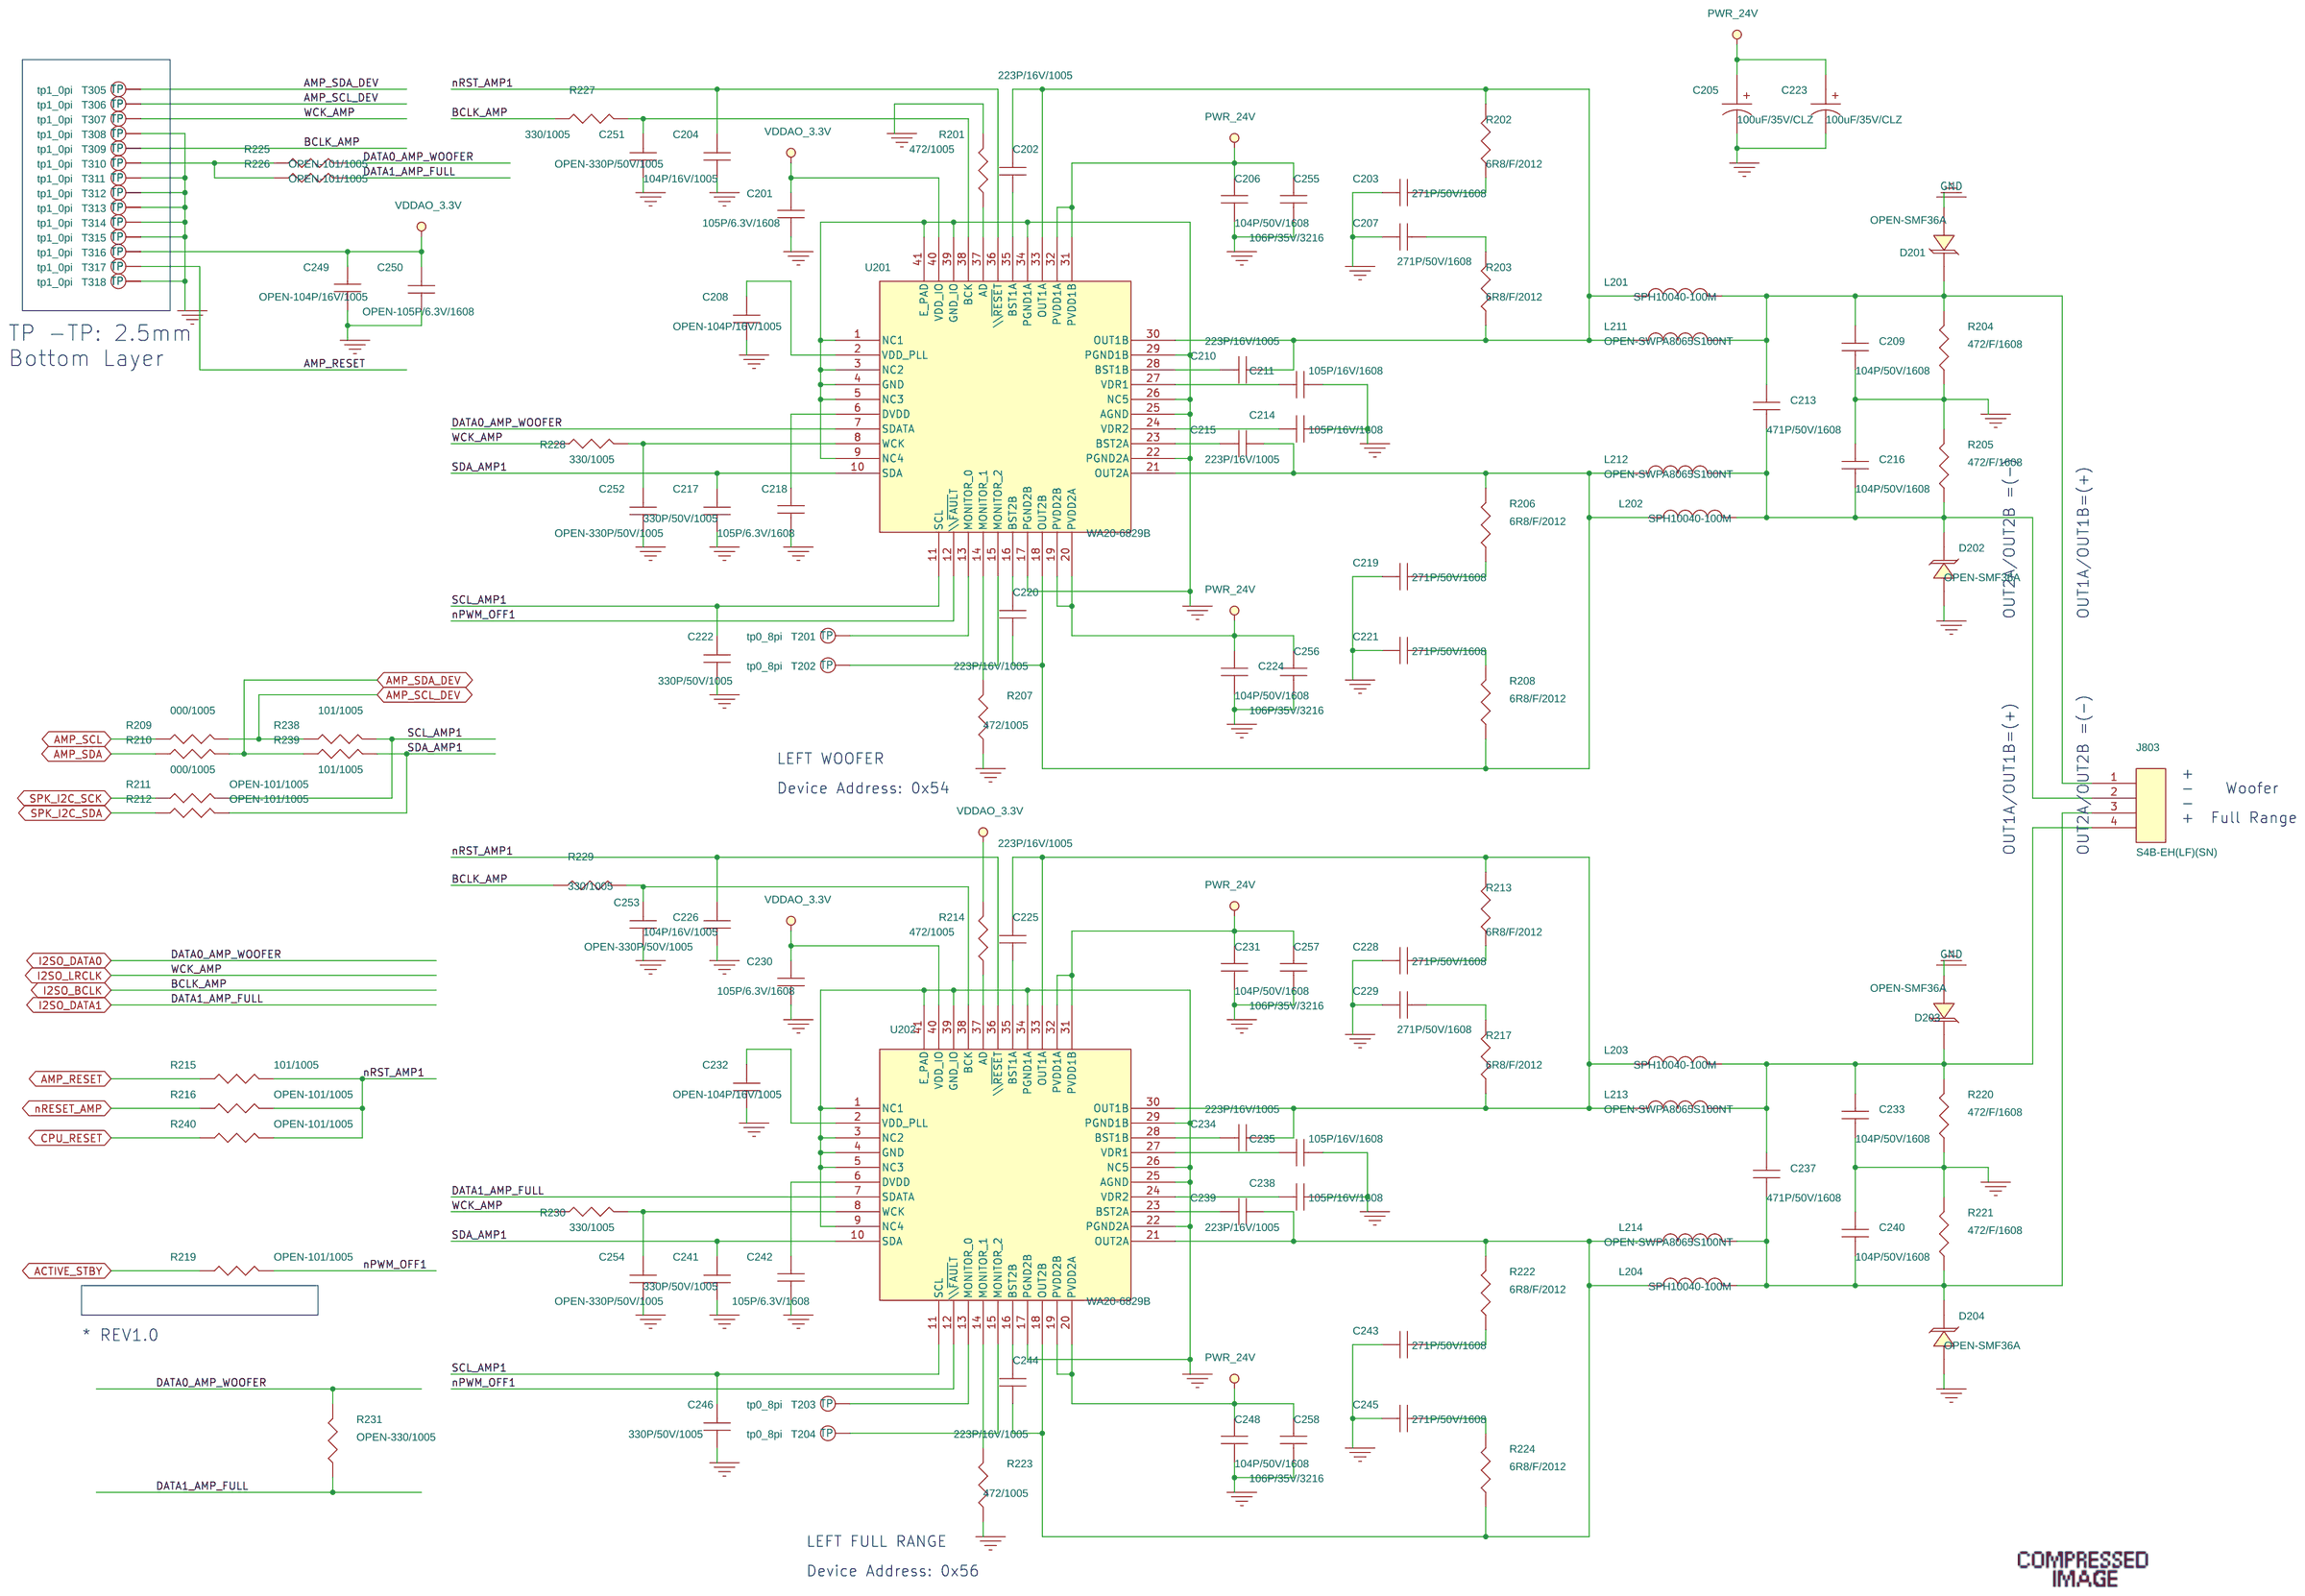
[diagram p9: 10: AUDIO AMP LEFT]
11 09: A113X_PERIPHERAL: size A3; title: 09. A113X_PERIPHERAL
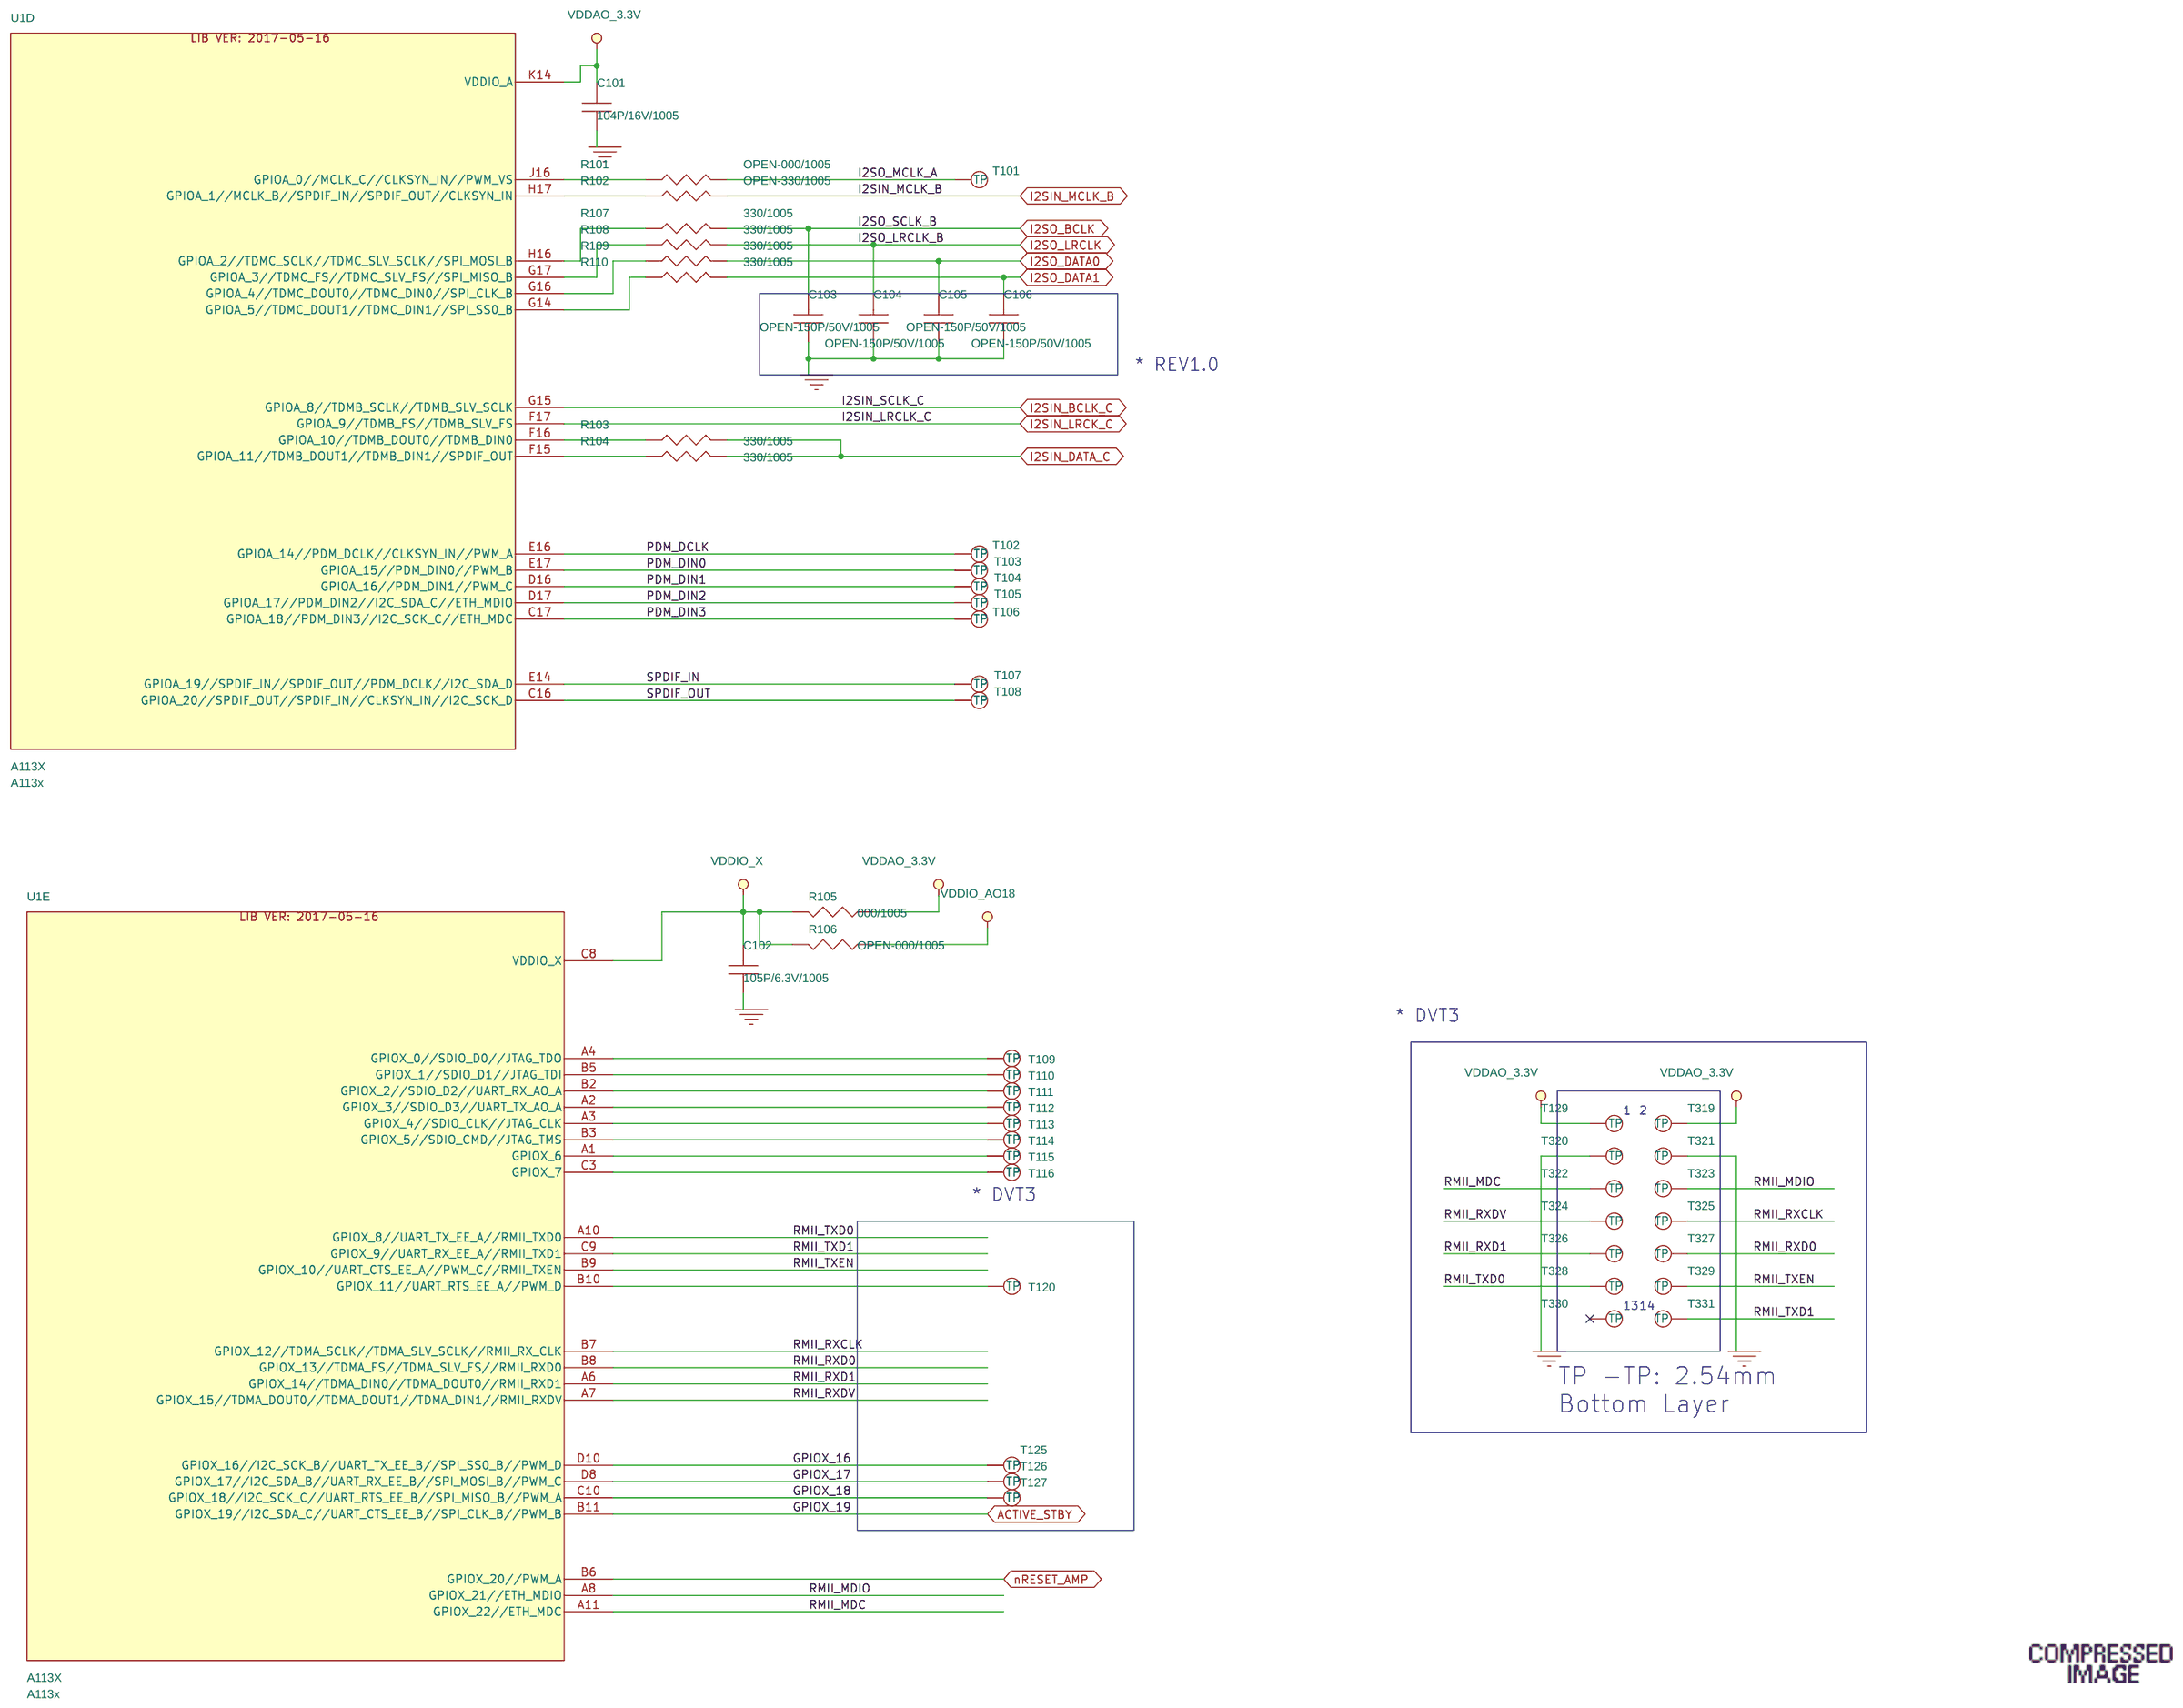
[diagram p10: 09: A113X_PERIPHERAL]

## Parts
sheet 03: POWER PART1
C1  105P/50V/1608  [c1608]
C2  104P/50V/1608  [c1608]
C3  106P/50V/3225  [C3225]
C4  104P/50V/1608  [c1608]
C5  104P/16V/1005  [c1005]
C6  226P/10V/2012  [c2012]
C7  226P/10V/2012  [c2012]
C8  OPEN-226P/10V/2012  [c2012]
C9  104P/16V/1005  [c1005]
C10  470P/50V/1005  [c1005]
C11  223P/50V/1005  [c1005]
C12  OPEN-104P/16V/1005  [c1005]
C13  226P/10V/2012  [c2012]
C14  104P/16V/1005  [c1005]
C15  104P/16V/1005  [c1005]
C16  226P/6.3V/2012  [c2012]
C17  104P/16V/1005  [c1005]
C18  226P/6.3V/2012  [c2012]
C19  330P/50V/1005  [c1005]
C20  104P/16V/1005  [c1005]
C21  106P/6.3V/1608  [c1608]
C22  106P/6.3V/1608  [c1608]
C23  104P/16V/1005  [c1005]
C30  106P/50V/3225  [C3225]
J812  51318-0023L-001  [51318-0023L-001]
L1  SWPA6045S6R8MT  [SWPA6045S]
L2  MLPS-5035-4R7M-E-EH  [COIL_MLPS5035]
Q1  WPM3401  [sot23_lrt_w2_7_WPM3401]
Q2  OPEN-MMBT3904  [sot23_lrt_MMBT3904]
Q3  OPEN-MMBT3904  [sot23_lrt_MMBT3904]
R1  OPEN-204/F/1005  [r1005]
R2  OPEN-000/1005  [r1005]
R3  4992/F/1005  [r1005]
R6  104/1005  [r1005]
R7  OPEN-473/1005  [r1005]
R8  104/F/1005  [r1005]
R9  2212/F/1005  [r1005]
R10  364/F/1005  [r1005]
R11  4022/F/1005  [r1005]
R12  OPEN-103/1005  [r1005]
R13  472/1005  [r1005]
R15  OPEN-103/1005  [r1005]
R16  OPEN-103/1005  [r1005]
R17  OPEN-103/1005  [r1005]
R18  OPEN-103/1005  [r1005]
R19  OPEN-000/1005  [r1005]
R20  103/F/1005  [r1005]
T1  BPPM00121190172X0F  [COIL_BPPM00121190]
U2  MP2338GTL  [SOT583_MP2338]
U3  TMI3252S  [sot23-6p_TMI3252S]
sheet 04: POWER PART2
1R1  103/F/1005  [r1005]
1R2  103/F/1005  [r1005]
C51  226P/10V/2012  [c2012]
C52  104P/16V/1005  [c1005]
C53  104P/16V/1005  [c1005]
C54  226P/6.3V/2012  [c2012]
C55  104P/16V/1005  [c1005]
C56  226P/6.3V/2012  [c2012]
C57  226P/10V/2012  [c2012]
C58  104P/16V/1005  [c1005]
C59  104P/16V/1005  [c1005]
C60  226P/6.3V/2012  [c2012]
C61  104P/16V/1005  [c1005]
C62  226P/6.3V/2012  [c2012]
C63  270P/50V/1005  [c1005]
C64  270P/50V/1005  [c1005]
C65  104P/16V/1005  [c1005]
C66  102P/16V/1005  [c1005]
C67  102P/16V/1005  [c1005]
C68  226P/10V/2012  [c2012]
C69  104P/16V/1005  [c1005]
C70  104P/16V/1005  [c1005]
C71  226P/6.3V/2012  [c2012]
C72  104P/16V/1005  [c1005]
C73  226P/6.3V/2012  [c2012]
C74  330P/50V/1005  [c1005]
C75  OPEN-104P/16V/1005  [c1005]
C76  106P/6.3V/1608  [c1608]
C77  OPEN-106P/6.3V/1608  [c1608]
C78  472P/50V/1608  [c1608]
C79  OPEN-472P/50V/1608  [c1608]
L51  LVS404018-2R2M  [COIL_LVS404018]
L52  LVS404018-2R2M  [COIL_LVS404018]
L53  SMPI0402BW-3R3M  [COIL_SMPI0402BW]
Q4  MMBT3904  [sot23_lrt_MMBT3904]
Q5  MMBT3904  [sot23_lrt_MMBT3904]
R51  104/F/1005  [r1005]
R52  472/1005  [r1005]
R53  124/F/1005  [r1005]
R54  472/1005  [r1005]
R55  105/F/1005  [r1005]
R56  104/F/1005  [r1005]
R57  125/F/1005  [r1005]
R58  124/F/1005  [r1005]
R59  1213/F/1005  [r1005]
R60  1623/F/1005  [r1005]
R61  124/F/1005  [r1005]
R62  102/1005  [r1005]
R63  9532/F/1005  [r1005]
R329  103/1005  [r1005]
R330  103/1005  [r1005]
R331  000/1005  [r1005]
R332  103/1005  [r1005]
R333  103/1005  [r1005]
R334  000/2012  [r2012]
R335  OPEN-000/1005  [r1005]
R336  OPEN-000/1005  [r1005]
R337  OPEN-472/1005  [r1005]
U51  TMI3252S  [sot23-6p_TMI3252S]
U52  TMI3252S  [sot23-6p_TMI3252S]
U53  TMI3252S  [sot23-6p_TMI3252S]
U54  TMI6050-18  [sot23-5_TMI6050]
U55  OPEN-TMI6050-18  [sot23-5_TMI6050]
sheet 05: A113X_IO
2C1  105P/6.3V/1005  [C0402]
2C2  222P/16V/1005  [C0402]
2C3  150P/50V/1005  [c1005]
2C4  106P/6.3V/1608  [C0603]
2C5  104P/16V/1005  [C0402]
2C6  106P/6.3V/1608  [C0603]
2C7  104P/16V/1005  [C0402]
2C8  104P/16V/1005  [C0402]
2C9  150P/50V/1005  [c1005]
2C10  105P/6.3V/1005  [C0402]
2C11  105P/6.3V/1005  [C0402]
2C12  105P/6.3V/1005  [C0402]
2C13  106P/6.3V/1608  [C0603]
2C14  105P/6.3V/1005  [C0402]
2C15  104P/16V/1005  [c1005]
2C16  105P/6.3V/1005  [C0402]
2C17  106P/6.3V/1608  [C0603]
2C19  104P/16V/1005  [C0402]
2C20  105P/6.3V/1005  [C0402]
2C22  104P/16V/1005  [C0402]
2CON1  OPEN-HB11041  [hdr_4p]
2D3  SZESD7371HT1G  [SOD-323_SZESD7371HT1G]
2D4  SZESD7371HT1G  [SOD-323_SZESD7371HT1G]
2D7  OPEN-BL-HG036A-AV-TRB  [LED1608]
2Q1  OPEN-MMBT3904  [sot23_lrt_MMBT3904]
2R1  241/1005  [r1005]
2R2  OPEN-103/1005  [R0402]
2R3  753/F/1005  [R0402]
2R5  474/F/1005  [r1005]
2R8  OPEN-473/1005  [r1005]
2R10  220/F/1005  [r1005]
2R12  OPEN-241/F/1005  [r1005]
2R14  OPEN-104/1005  [r1005]
2R15  243/F/1005  [R0402]
2R16  241/1005  [r1005]
2R18  152/1005  [r1005]
2R19  152/1005  [r1005]
2R24  152/1005  [r1005]
2R27  000/1005  [TEST_R]
2R28  152/1005  [r1005]
2R29  472/1005  [r1005]
2T3  T_POINT_R_1  [tp0_8pi]
2T5  T_POINT_R_1  [tp0_8pi]
2T6  T_POINT_R_1  [tp0_8pi]
2T7  T_POINT_R_1  [tp0_8pi]
2T8  T_POINT_R_1  [tp0_8pi]
2T15  T_POINT_R_1  [tp1_0pi]
2T16  T_POINT_R_1  [tp1_0pi]
2T17  T_POINT_R_1  [tp1_0pi]
2T18  T_POINT_R_1  [tp1_0pi]
2T19  T_POINT_R_1  [tp1_0pi]
2T20  T_POINT_R_1  [tp1_0pi]
2T21  T_POINT_R_1  [tp1_0pi]
2T22  T_POINT_R_1  [tp1_0pi]
2T23  T_POINT_R_1  [tp1_0pi]
2T24  T_POINT_R_1  [tp1_0pi]
2T25  T_POINT_R_1  [tp1_0pi]
2T26  T_POINT_R_1  [tp1_0pi]
2T27  T_POINT_R_1  [tp1_0pi]
2T28  T_POINT_R_1  [tp1_0pi]
2T29  T_POINT_R_1  [tp0_8pi]
2U2  DIO6809RST3  [sot23_lrt_DIO6809RST3]
2Y2  24MHz_CL12PF_3225  [XTAL3225]
sheet 06: A113X_DDR3L
3C1  105P/6.3V/1005  [C0402]
3C2  105P/6.3V/1005  [C0402]
3C4  104P/16V/1005  [C0402]
3C5  105P/6.3V/1005  [C0402]
3C6  106P/6.3V/1608  [C0603]
3C7  2R2P/50V/1005  [C0402]
3C8  106P/6.3V/1608  [C0603]
3C9  104P/16V/1005  [C0402]
3C10  104P/16V/1005  [C0402]
3C11  104P/16V/1005  [C0402]
3C12  105P/6.3V/1005  [C0402]
3C18  105P/6.3V/1005  [C0402]
3C19  105P/6.3V/1005  [C0402]
3C20  104P/16V/1005  [C0402]
3C21  105P/6.3V/1005  [C0402]
3C26  106P/6.3V/1608  [C0603]
3C27  104P/16V/1005  [C0402]
3C28  106P/6.3V/1608  [C0603]
3C30  102P/50V/1005  [C0402]
3C31  104P/16V/1005  [C0402]
3C35  105P/6.3V/1005  [C0402]
3C38  105P/6.3V/1005  [C0402]
3C39  104P/16V/1005  [C0402]
3C40  104P/16V/1005  [C0402]
3C42  104P/16V/1005  [C0402]
3C45  104P/16V/1005  [C0402]
3C46  105P/6.3V/1005  [C0402]
3C58  101P/50V/1005  [C0402]
3C62  105P/6.3V/1005  [C0402]
3R2  OPEN-151/1005  [R0402]
3R6  241/F/1005  [R0402]
3R8  OPEN-103/1005  [R0402]
3R10  241/F/1005  [R0402]
3R19  102/F/1005  [R0402]
3R20  102/F/1005  [R0402]
3T1  T_POINT_R_1  [TP12]
3U1  H5TC4G63CFR-RDC  [bga96_H5TC4G63CFR-RDC]
sheet 07: A113X_FLASH
4C2  105P/6.3V/1005  [C0402]
4C3  OPEN-6R8P/50V/1005  [c1005]
4C4  104P/16V/1005  [c1005]
4C5  475P/6.3V/1608  [c1608]
4C8  104P/16V/1005  [c1005]
4C9  104P/16V/1005  [c1005]
4C10  104P/16V/1005  [c1005]
4C11  104P/16V/1005  [c1005]
4C17  OPEN-104P/16V/1005  [c1005]
4C18  OPEN-105P/6.3V/1005  [c1005]
4C26  OPEN-105P/6.3V/1005  [c1005]
4C34  OPEN-104P/16V/1005  [c1005]
4C35  OPEN-105P/6.3V/1005  [c1005]
4C47  OPEN-475P/6.3V/1608  [c1608]
4C48  104P/16V/1005  [c1005]
4C49  104P/16V/1005  [c1005]
4K2  TS-1187-1716  [SW_TS-1187]
4R1  OPEN-103/1005  [r1005]
4R2  OPEN-472/1005  [r1005]
4R3  000/1005  [r1005]
4R4  473/1005  [r1005]
4R5  OPEN-000/1005  [r1005]
4R6  000/1005  [r1005]
4R7  000/1005  [r1005]
4R8  OPEN-000/1005  [r1005]
4R9  OPEN-103/1005  [r1005]
4R10  472/1005  [r1005]
4R11  OPEN-000/1005  [r1005]
4R12  103/1005  [r1005]
4R13  OPEN-472/1005  [r1005]
4R14  OPEN-472/1005  [r1005]
4R15  OPEN-000/1005  [r1005]
4R16  OPEN-472/1005  [r1005]
4R17  OPEN-000/1005  [r1005]
4R18  OPEN-000/1005  [r1005]
4R19  OPEN-000/1005  [r1005]
4R20  OPEN-000/1005  [r1005]
4R21  OPEN-000/1005  [r1005]
4R22  OPEN-000/1005  [r1005]
4R23  OPEN-000/1005  [r1005]
4R24  OPEN-000/1005  [r1005]
4R25  OPEN-000/1005  [r1005]
4R26  OPEN-000/1005  [r1005]
4R52  OPEN-472/1005  [r1005]
4T25  T_POINT_R_1  [tp0_8pi]
4U5  MX30LF4G28AD_TI  [tsop48_w20_MX30LF4G28AD-TI]
4U9  OPEN-S40FC004C181C  [bga153_S40FC004C181C]  (sections A,B)
sheet 08: A113X_POWER
5C3  105P/6.3V/1005  [c1005]
5C9  104P/16V/1005  [C0402]
5C10  104P/16V/1005  [C0402]
5C11  105P/6.3V/1005  [c1005]
5C13  104P/16V/1005  [c1005]
5D11  SZESD7371HT1G  [SOD-323_SZESD7371HT1G]
5D12  SZESD7371HT1G  [SOD-323_SZESD7371HT1G]
5R5  102/1005  [r1005]
5R20  OPEN-103/1005  [r1005]
5R64  201/F/1005  [R0402]
5R65  330/1005  [r1005]
5R66  330/1005  [r1005]
5R67  330/1005  [r1005]
5R68  330/1005  [r1005]
5R69  330/1005  [r1005]
5R70  330/1005  [r1005]
5R71  5R1/F/1005  [r1005]
5R72  5R1/F/1005  [r1005]
5R73  330/1005  [r1005]
5R74  330/1005  [r1005]
5R75  330/1005  [r1005]
5R76  OPEN-101/1005  [r1005]
5R77  OPEN-101/1005  [r1005]
5R78  OPEN-103/1005  [r1005]
5R83  102/1005  [r1005]
5R84  5R1/F/1005  [r1005]
5R85  5R1/F/1005  [r1005]
J813  FH41-15S-0.5SH(05)  [FH41-15S-0_5SH]
J814  10118192-0002LF  [MICRO_USB_10118192]
sheet 09: A113X_PERIPHERAL
C101  104P/16V/1005  [C0402]
C102  105P/6.3V/1005  [C0402]
C103  OPEN-150P/50V/1005  [c1005]
C104  OPEN-150P/50V/1005  [c1005]
C105  OPEN-150P/50V/1005  [c1005]
C106  OPEN-150P/50V/1005  [c1005]
R101  OPEN-000/1005  [r1005]
R102  OPEN-330/1005  [r1005]
R103  330/1005  [r1005]
R104  330/1005  [r1005]
R105  000/1005  [r1005]
R106  OPEN-000/1005  [r1005]
R107  330/1005  [r1005]
R108  330/1005  [r1005]
R109  330/1005  [r1005]
R110  330/1005  [r1005]
T101  T_POINT_R_1  [tp0_8pi]
T102  T_POINT_R_1  [tp0_8pi]
T103  T_POINT_R_1  [tp0_8pi]
T104  T_POINT_R_1  [tp0_8pi]
T105  T_POINT_R_1  [tp0_8pi]
T106  T_POINT_R_1  [tp0_8pi]
T107  T_POINT_R_1  [tp0_8pi]
T108  T_POINT_R_1  [tp0_8pi]
T109  T_POINT_R_1  [tp0_8pi]
T110  T_POINT_R_1  [tp0_8pi]
T111  T_POINT_R_1  [tp0_8pi]
T112  T_POINT_R_1  [tp0_8pi]
T113  T_POINT_R_1  [tp0_8pi]
T114  T_POINT_R_1  [tp0_8pi]
T115  T_POINT_R_1  [tp0_8pi]
T116  T_POINT_R_1  [tp0_8pi]
T120  T_POINT_R_1  [tp0_8pi]
T125  T_POINT_R_1  [tp0_8pi]
T126  T_POINT_R_1  [tp0_8pi]
T127  T_POINT_R_1  [tp0_8pi]
T129  T_POINT_R_1  [TP1_0PI]
T319  T_POINT_R_1  [TP1_0PI]
T320  T_POINT_R_1  [TP1_0PI]
T321  T_POINT_R_1  [TP1_0PI]
T322  T_POINT_R_1  [TP1_0PI]
T323  T_POINT_R_1  [TP1_0PI]
T324  T_POINT_R_1  [TP1_0PI]
T325  T_POINT_R_1  [TP1_0PI]
T326  T_POINT_R_1  [TP1_0PI]
T327  T_POINT_R_1  [TP1_0PI]
T328  T_POINT_R_1  [TP1_0PI]
T329  T_POINT_R_1  [TP1_0PI]
T330  T_POINT_R_1  [TP1_0PI]
T331  T_POINT_R_1  [TP1_0PI]
U1  A113X  [A113x]  (sections A,B,C,D,E,F,G)
sheet 10: AUDIO AMP LEFT
C201  105P/6.3V/1608  [c1608]
C202  223P/16V/1005  [c1005]
C203  271P/50V/1608  [c1608]
C204  104P/16V/1005  [c1005]
C205  100uF/35V/CLZ  [ecap_8pi_h10]
C206  104P/50V/1608  [c1608]
C207  271P/50V/1608  [c1608]
C208  OPEN-104P/16V/1005  [c1005]
C209  104P/50V/1608  [c1608]
C210  223P/16V/1005  [c1005]
C211  105P/16V/1608  [c1608]
C213  471P/50V/1608  [c1608]
C214  105P/16V/1608  [c1608]
C215  223P/16V/1005  [c1005]
C216  104P/50V/1608  [c1608]
C217  330P/50V/1005  [c1005]
C218  105P/6.3V/1608  [c1608]
C219  271P/50V/1608  [c1608]
C220  223P/16V/1005  [c1005]
C221  271P/50V/1608  [c1608]
C222  330P/50V/1005  [c1005]
C223  100uF/35V/CLZ  [ecap_8pi_h10]
C224  104P/50V/1608  [c1608]
C225  223P/16V/1005  [c1005]
C226  104P/16V/1005  [c1005]
C228  271P/50V/1608  [c1608]
C229  271P/50V/1608  [c1608]
C230  105P/6.3V/1608  [c1608]
C231  104P/50V/1608  [c1608]
C232  OPEN-104P/16V/1005  [c1005]
C233  104P/50V/1608  [c1608]
C234  223P/16V/1005  [c1005]
C235  105P/16V/1608  [c1608]
C237  471P/50V/1608  [c1608]
C238  105P/16V/1608  [c1608]
C239  223P/16V/1005  [c1005]
C240  104P/50V/1608  [c1608]
C241  330P/50V/1005  [c1005]
C242  105P/6.3V/1608  [c1608]
C243  271P/50V/1608  [c1608]
C244  223P/16V/1005  [c1005]
C245  271P/50V/1608  [c1608]
C246  330P/50V/1005  [c1005]
C248  104P/50V/1608  [c1608]
C249  OPEN-105P/6.3V/1608  [c1608]
C250  OPEN-104P/16V/1005  [c1005]
C251  OPEN-330P/50V/1005  [c1005]
C252  OPEN-330P/50V/1005  [c1005]
C253  OPEN-330P/50V/1005  [c1005]
C254  OPEN-330P/50V/1005  [c1005]
C255  106P/35V/3216  [C3216]
C256  106P/35V/3216  [C3216]
C257  106P/35V/3216  [C3216]
C258  106P/35V/3216  [C3216]
D201  OPEN-SMF36A  [sod123fl_SMF36A]
D202  OPEN-SMF36A  [sod123fl_SMF36A]
D203  OPEN-SMF36A  [sod123fl_SMF36A]
D204  OPEN-SMF36A  [sod123fl_SMF36A]
J803  S4B-EH(LF)(SN)  [SXB-EH-4P]
L201  SPH10040-100M  [COIL_SPH10040]
L202  SPH10040-100M  [COIL_SPH10040]
L203  SPH10040-100M  [COIL_SPH10040]
L204  SPH10040-100M  [COIL_SPH10040]
L211  OPEN-SWPA8065S100NT  [SWPA8065S]
L212  OPEN-SWPA8065S100NT  [SWPA8065S]
L213  OPEN-SWPA8065S100NT  [SWPA8065S]
L214  OPEN-SWPA8065S100NT  [SWPA8065S]
R201  472/1005  [r1005]
R202  6R8/F/2012  [r2012]
R203  6R8/F/2012  [r2012]
R204  472/F/1608  [r1608]
R205  472/F/1608  [r1608]
R206  6R8/F/2012  [r2012]
R207  472/1005  [r1005]
R208  6R8/F/2012  [r2012]
R209  000/1005  [r1005]
R210  000/1005  [r1005]
R211  OPEN-101/1005  [r1005]
R212  OPEN-101/1005  [r1005]
R213  6R8/F/2012  [r2012]
R214  472/1005  [r1005]
R215  101/1005  [r1005]
R216  OPEN-101/1005  [r1005]
R217  6R8/F/2012  [r2012]
R219  OPEN-101/1005  [r1005]
R220  472/F/1608  [r1608]
R221  472/F/1608  [r1608]
R222  6R8/F/2012  [r2012]
R223  472/1005  [r1005]
R224  6R8/F/2012  [r2012]
R225  OPEN-101/1005  [r1005]
R226  OPEN-101/1005  [r1005]
R227  330/1005  [r1005]
R228  330/1005  [r1005]
R229  330/1005  [r1005]
R230  330/1005  [r1005]
R231  OPEN-330/1005  [r1005]
R238  101/1005  [r1005]
R239  101/1005  [r1005]
R240  OPEN-101/1005  [r1005]
T201  T_POINT_R_1  [tp0_8pi]
T202  T_POINT_R_1  [tp0_8pi]
T203  T_POINT_R_1  [tp0_8pi]
T204  T_POINT_R_1  [tp0_8pi]
T305  T_POINT_R_1  [tp1_0pi]
T306  T_POINT_R_1  [tp1_0pi]
T307  T_POINT_R_1  [tp1_0pi]
T308  T_POINT_R_1  [tp1_0pi]
T309  T_POINT_R_1  [tp1_0pi]
T310  T_POINT_R_1  [tp1_0pi]
T311  T_POINT_R_1  [tp1_0pi]
T312  T_POINT_R_1  [tp1_0pi]
T313  T_POINT_R_1  [tp1_0pi]
T314  T_POINT_R_1  [tp1_0pi]
T315  T_POINT_R_1  [tp1_0pi]
T316  T_POINT_R_1  [tp1_0pi]
T317  T_POINT_R_1  [tp1_0pi]
T318  T_POINT_R_1  [tp1_0pi]
U201  WA20-6829B  [QFN40_p0_5_w6_WA20-6829B]
U202  WA20-6829B  [QFN40_p0_5_w6_WA20-6829B]
sheet 11: AUDIO AMP RIGHT
C301  105P/6.3V/1608  [c1608]
C302  223P/16V/1005  [c1005]
C303  271P/50V/1608  [c1608]
C304  104P/16V/1005  [c1005]
C305  100uF/35V/CLZ  [ecap_8pi_h10]
C306  104P/50V/1608  [c1608]
C307  271P/50V/1608  [c1608]
C308  OPEN-104P/16V/1005  [c1005]
C309  104P/50V/1608  [c1608]
C310  223P/16V/1005  [c1005]
C311  105P/16V/1608  [c1608]
C313  471P/50V/1608  [c1608]
C314  105P/16V/1608  [c1608]
C315  223P/16V/1005  [c1005]
C316  104P/50V/1608  [c1608]
C317  330P/50V/1005  [c1005]
C318  105P/6.3V/1608  [c1608]
C319  271P/50V/1608  [c1608]
C320  223P/16V/1005  [c1005]
C321  271P/50V/1608  [c1608]
C322  330P/50V/1005  [c1005]
C323  100uF/35V/CLZ  [ecap_8pi_h10]
C324  104P/50V/1608  [c1608]
C325  223P/16V/1005  [c1005]
C326  104P/16V/1005  [c1005]
C328  271P/50V/1608  [c1608]
C329  271P/50V/1608  [c1608]
C330  105P/6.3V/1608  [c1608]
C331  104P/50V/1608  [c1608]
C332  OPEN-104P/16V/1005  [c1005]
C333  104P/50V/1608  [c1608]
C334  223P/16V/1005  [c1005]
C335  105P/16V/1608  [c1608]
C337  471P/50V/1608  [c1608]
C338  105P/16V/1608  [c1608]
C339  223P/16V/1005  [c1005]
C340  104P/50V/1608  [c1608]
C341  330P/50V/1005  [c1005]
C342  105P/6.3V/1608  [c1608]
C343  271P/50V/1608  [c1608]
C344  223P/16V/1005  [c1005]
C345  271P/50V/1608  [c1608]
C346  330P/50V/1005  [c1005]
C348  104P/50V/1608  [c1608]
C349  OPEN-330P/50V/1005  [c1005]
C350  OPEN-330P/50V/1005  [c1005]
C351  OPEN-330P/50V/1005  [c1005]
C352  OPEN-330P/50V/1005  [c1005]
C353  106P/35V/3216  [C3216]
C354  106P/35V/3216  [C3216]
C355  106P/35V/3216  [C3216]
C356  106P/35V/3216  [C3216]
D301  OPEN-SMF36A  [sod123fl_SMF36A]
D302  OPEN-SMF36A  [sod123fl_SMF36A]
D303  OPEN-SMF36A  [sod123fl_SMF36A]
D304  OPEN-SMF36A  [sod123fl_SMF36A]
J804  S4B-EH(LF)(SN)  [SXB-EH-4P]
L301  SPH10040-100M  [COIL_SPH10040]
L302  SPH10040-100M  [COIL_SPH10040]
L303  SPH10040-100M  [COIL_SPH10040]
L304  SPH10040-100M  [COIL_SPH10040]
L311  OPEN-SWPA8065S100NT  [SWPA8065S]
L312  OPEN-SWPA8065S100NT  [SWPA8065S]
L313  OPEN-SWPA8065S100NT  [SWPA8065S]
L314  OPEN-SWPA8065S100NT  [SWPA8065S]
R301  472/1005  [r1005]
R302  6R8/F/2012  [r2012]
R303  6R8/F/2012  [r2012]
R304  472/F/1608  [r1608]
R305  472/F/1608  [r1608]
R306  6R8/F/2012  [r2012]
R307  472/1005  [r1005]
R308  6R8/F/2012  [r2012]
R309  101/1005  [r1005]
R310  101/1005  [r1005]
R311  OPEN-101/1005  [r1005]
R312  OPEN-101/1005  [r1005]
R313  6R8/F/2012  [r2012]
R314  472/1005  [r1005]
R315  101/1005  [r1005]
R316  OPEN-101/1005  [r1005]
R317  6R8/F/2012  [r2012]
R319  472/F/1608  [r1608]
R320  OPEN-101/1005  [r1005]
R321  472/F/1608  [r1608]
R322  6R8/F/2012  [r2012]
R323  472/1005  [r1005]
R324  6R8/F/2012  [r2012]
R325  330/1005  [r1005]
R326  330/1005  [r1005]
R327  330/1005  [r1005]
R328  330/1005  [r1005]
R338  OPEN-101/1005  [r1005]
T301  T_POINT_R_1  [tp0_8pi]
T302  T_POINT_R_1  [tp0_8pi]
T303  T_POINT_R_1  [tp0_8pi]
T304  T_POINT_R_1  [tp0_8pi]
U301  WA20-6829B  [QFN40_p0_5_w6_WA20-6829B]
U302  WA20-6829B  [QFN40_p0_5_w6_WA20-6829B]

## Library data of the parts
2C4 2C6 2C13 2C17 3C6 3C8 3C26 3C28 4C5 4C47 C1-C4 C21 C22 C30 C76-C79 C201 C203 C206 C207 C209 C211 C213 C214 C216 C218 C219 C221 C224 C228-C231 C233 C235 C237 C238 C240 C242 C243 C245 C248 C249 C255-C258 C301 C303 C306 C307 C309 C311 C313 C314 C316 C318 C319 C321 C324 C328-C331 C333 C335 C337 C338 C340 C342 C343 C345 C348 C353-C356 = MLCC_1608_0: Part Type: MLCC
2C1-2C3 2C5 2C7-2C12 2C14-2C16 2C19 2C20 2C22 3C1 3C2 3C4 3C5 3C7 3C9-3C12 3C18-3C21 3C27 3C30 3C31 3C35 3C38-3C40 3C42 3C45 3C46 3C58 3C62 4C2-4C4 4C8-4C11 4C17 4C18 4C26 4C34 4C35 4C48 4C49 5C3 5C9-5C11 5C13 C5 C9-C12 C14 C15 C17 C19 C20 C23 C52 C53 C55 C58 C59 C61 C63-C67 C69 C70 C72 C74 C75 C101-C106 C202 C204 C208 C210 C215 C217 C220 C222 C225 C226 C232 C234 C239 C241 C244 C246 C250-C254 C302 C304 C308 C310 C315 C317 C320 C322 C325 C326 C332 C334 C339 C341 C344 C346 C349-C352 = MLCC_1005_0: Part Type: MLCC
C6-C8 C13 C16 C18 C51 C54 C56 C57 C60 C62 C68 C71 C73 = MLCC_2012_0: Part Type: MLCC
J812 = CON_HEADER_1X4_1: Manufacturer: ACES ELECTRONICS; OTHER: 3; Part Type: PIN HEADER
L1 = INDUCTOR_CHIP_0: Manufacturer: SUNLOAD; OTHER: 1; Part Type: IND POWER
L2 = INDUCTOR_CHIP_0: Manufacturer: MAG LAYER; OTHER: 1; Part Type: IND POWER
Q1 = P-MOSFET: Manufacturer: WILLSEMI; Manufacturer Part Number: WPM3401-3/TR; Part type: P-CH MOSFET
2Q1 Q2-Q5 = npn: Manufacturer: PANJIT; Manufacturer Part Number: MMBT-3904; Part Type: TR NPN
1R1 1R2 2R1-2R3 2R5 2R8 2R10 2R12 2R14-2R16 2R18 2R19 2R24 2R27-2R29 3R2 3R6 3R8 3R10 3R19 3R20 4R1-4R26 4R52 5R5 5R20 5R64-5R78 5R83-5R85 R1-R3 R6-R13 R15-R20 R51-R63 R101-R110 R201-R217 R219-R231 R238-R240 R301-R317 R319-R338 = RES-V: Part Type: RES SMD
T1 = FILTER_EMI_DLW21SN900SQ2_0: Manufacturer: HILISIN; OTHER: 1
U2 = MP2338GTL
U3 U51-U53 = SY81XX: Manufacturer: TMI SUNTO; Part Type: IC DC-DC
L51 L52 = INDUCTOR_CHIP_0: Manufacturer: CHILISIN; OTHER: 1; Part Type: IND POWER
L53 = INDUCTOR_CHIP_0: Manufacturer: HANGHSING; OTHER: 1; Part Type: IND POWER
U54 = WL2003E: Manufacturer: TMI SUNTO; Part Type: IC LDO
U55 = WL2003E: Manufacturer: TMI SUNTO; Manufacturer Part Number: TMI6050-18; Part Type: IC LDO
2CON1 = CN-4P_0: Manufacturer: CJT; Manufacturer Part Number: A2501WV-4P; Part Type: HEADER_1x4_2.5
2D3 2D4 5D11 5D12 = TVS_DIODE: Manufacturer: ON SEMI; Part Type: TVS DIODE
2D7 = LED_3: Manufacturer: BRIGHT LED; Manufacturer Part Number: BL-HG036A-AV-TRB; Part Type: LED SMD
2T3 2T5-2T8 2T15-2T29 3T1 4T25 T101-T116 T120 T125-T127 T129 T201-T204 T301-T331 = T_POINT_R_1: Part Type: TP
2U2 = MAX809RD: Manufacturer: DIOO; Part Type: IC RESET
2Y2 = SMD_CRYSTAL: Manufacturer: JINGYUAN; Manufacturer Part Number: JYD3A1E7I9-9-24.000; Part Type: CRYSTAL SMD
3U1 = DDR3_96P_16b_0: Manufacturer: SK HYNIX; Part Type: IC DDR3L
4K2 = BUTTON_0: Manufacturer: SOFNG; Part Type: TACT SWITCH_SMD
4U5 = NAND-ALL_11: Manufacturer: MACRONIX; Part Type: IC SLC NAND
4U9 = eMMC_V5_0.1: Manufacturer: SKYHIGH; Manufacturer Part Number: S40FC004C181C; Part Type: IC EMMC
J813 = CON15X1-4G_0: MANUFACTURER: HIROSE; Part Type: FFC HEADER SMD
J814 = JP_USB-0400ASMT_0
U1 = A113X_20170516_V17: Color: Default; Location X-Coordinate: 0; Location Y-Coordinate: 0; Manufacturer: AMLOGIC; Manufacturer Part Number: A113X-B; Part Type: IC AUDIO DSP; Power Pins Visible: False; Primitive: DEFAULT; OriginalSymbolOrigin: LFBGA 284
C205 C223 C305 C323 = ECAP-2.5X6.3-D: Manufacturer: SAMYOUNG; Manufacturer Part Number: CLZ35VC101MH10TP; Part Type: ECAP SMD
D201-D204 D301-D304 = DIO-TVS-A: MANUFACTURER: PANJIT; Manufacturer Part Number: SMF36A; Part Type: TVS DIODE
J803 J804 = CON4: MANUFACTURER: JST; Part Type: HEADER_1X4_2.5RA
L201-L204 L301-L304 = INDUCTOR_CHIP_0: Manufacturer: LS COMM; OTHER: 1; Part Type: IND POWER
L211-L214 L311-L314 = INDUCTOR_CHIP_0: Manufacturer: SUNLOAD; Manufacturer Part Number: SPH10040-100M; OTHER: 1; Part Type: IND POWER
U201 U202 U301 U302 = WA20-6829B_0: Manufacturer: WELLANG; Part Type: IC CLASS D AMP

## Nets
5V_EN: 5R73.2 C12.2 R1.1 R2.1 R2.2 R3.2 U2.6(EN)
GND: 2C1.1 2C2.1 2C3.1 2C4.2 2C5.1 2C6.2 2C7.1 2C8.1 2C9.1 2C10.1 2C11.1 2C12.1 2C13.2 2C14.1 2C15.1 2C16.1 2C17.2 2C19.1 2C20.1 2C22.1 2CON1.1 2D3.2 2D4.2 2Q1.2(EMITTER) 2R14.2 2R15.1 2T17.1(TP) 2T25.1(TP) 2T28.1(TP) 2U2.1(GND) 2Y2.2 2Y2.4 3C1.1 3C2.1 3C4.1 3C5.1 3C6.2 3C8.2 3C9.1 3C10.1 3C11.1 3C12.1 3C18.1 3C19.1 3C20.1 3C21.1 3C26.2 3C27.1 3C28.2 3C30.1 3C31.1 3C35.1 3C38.1 3C39.1 3C40.1 3C42.1 3C45.1 3C46.1 3C58.1 3C62.1 3R6.1 3R10.1 3R20.1 3U1.A9(VSS) 3U1.B1(VSSQ) 3U1.B3(VSS) 3U1.B9(VSSQ) 3U1.D1(VSSQ) 3U1.D8(VSSQ) 3U1.E1(VSS) 3U1.E2(VSSQ) 3U1.E8(VSSQ) 3U1.F9(VSSQ) 3U1.G1(VSSQ) 3U1.G8(VSS) 3U1.G9(VSSQ) 3U1.J2(VSS) 3U1.J8(VSS) 3U1.M1(VSS) 3U1.M9(VSS) 3U1.P1(VSS) 3U1.P9(VSS) 3U1.T1(VSS) 3U1.T9(VSS) 4C2.1 4C3.1 4C4.1 4C5.2 4C8.1 4C9.1 4C10.1 4C11.1 4C17.1 4C18.1 4C26.1 4C34.1 4C35.1 4C47.2 4C48.1 4C49.1 4K2.1 4K2.2 4R2.1 4R7.1 4R9.2 4R13.1 4R52.1 4U5.2(NC_//_Vpp//_VSS) 4U5.13(VSS1) 4U5.23(NC_//_Vpp//_VSS2) 4U5.25(NC_//_VSSQ_//_VSS3) 4U5.27((I/O9)_//_VSS) 4U5.33((I/O11)_//_VSS) 4U5.36(VSS2) 4U5.40((I/O12)_//_VSS) 4U5.46((I/O14)_//_VSS) 4U5.48(NC_//_VSSQ_//_VSS4) 4U9.AA4(VSSQ4) 4U9.AA6(VSSQ5) 4U9.H6(VSS5) 4U9.K4(VSSQ1) 4U9.M7(VSS1) 4U9.P5(VSS2) 4U9.R10(VSS3) 4U9.T5(VSS6) 4U9.U8(VSS4) 4U9.Y2(VSSQ2) 4U9.Y5(VSSQ3) 5C3.1 5C9.1 5C10.1 5C11.1 5C13.1 5D11.2 5D12.2 5R64.2 5R78.2 C1.2 C2.2 C3.2 C4.2 C6.2 C7.2 C8.2 C9.1 C11.1 C12.1 C13.2 C14.1 C16.2 C17.1 C18.2 C20.1 C21.2 C22.2 C30.2 C51.2 C52.1 C54.2 C55.1 C56.2 C57.2 C58.1 C60.2 C61.1 C62.2 C65.1 C66.1 C67.1 C68.2 C69.1 C71.2 C72.1 C73.2 C75.1 C76.2 C77.2 C78.2 C79.2 C101.1 C102.1 C103.1 C104.1 C105.1 C106.1 C201.2 C203.1 C204.1 C205.2 C206.2 C207.1 C208.1 C209.2 C211.2 C214.2 C216.1 C217.1 C218.2 C219.1 C221.1 C222.1 C223.2 C224.2 C226.1 C228.1 C229.1 C230.2 C231.2 C232.1 C233.2 C235.2 C238.2 C240.1 C241.1 C242.2 C243.1 C245.1 C246.1 C248.2 C249.2 C250.1 C251.1 C252.1 C253.1 C254.1 C255.2 C256.2 C257.2 C258.2 C301.2 C303.1 C304.1 C305.2 C306.2 C307.1 C308.1 C309.2 C311.2 C314.2 C316.1 C317.1 C318.2 C319.1 C321.1 C322.1 C323.2 C324.2 C326.1 C328.1 C329.1 C330.2 C331.2 C332.1 C333.2 C335.2 C338.2 C340.1 C341.1 C342.2 C343.1 C345.1 C346.1 C348.2 C349.1 C350.1 C351.1 C352.1 C353.2 C354.2 C355.2 C356.2 D201.2 D202.2 D203.2 D204.2 D301.2 D302.2 D303.2 D304.2 J813.3 J813.9 J813.13 J813.15 J813.S1 J813.S2 J813.S3 J813.S4 J813.S5 J814.5(GND) J814.6(S1) J814.7(S2) J814.8(S3) J814.9(S4) J814.10(S5) J814.11(S6) Q2.2(EMITTER) Q3.2(EMITTER) Q4.2(EMITTER) Q5.2(EMITTER) R3.1 R7.1 R9.1 R11.1 R59.1 R60.1 R63.1 R201.2 R204.1 R205.2 R207.1 R220.1 R221.2 R223.1 R301.2 R304.1 R305.2 R319.1 R321.2 T1.2 T308.1(TP) T311.1(TP) T312.1(TP) T313.1(TP) T314.1(TP) T315.1(TP) T318.1(TP) T320.1(TP) T321.1(TP) U1.A9(DVSS) U1.A14(DVSS) U1.B4(DVSS) U1.B17(DVSS) U1.D5(DVSS) U1.D7(DVSS) U1.D9(DVSS) U1.D12(DVSS) U1.D14(DVSS) U1.E4(DVSS) U1.E5(DVSS) U1.E6(DVSS) U1.E7(DVSS) U1.E8(DVSS) U1.E9(DVSS) U1.E10(DVSS) U1.E11(DVSS) U1.E12(DVSS) U1.E13(DVSS) U1.F3(DVSS) U1.F4(DVSS) U1.F7(DVSS) U1.F8(DVSS) U1.F9(DVSS) U1.F10(DVSS) U1.F11(DVSS) U1.F14(DVSS) U1.G7(DVSS) U1.G8(DVSS) U1.G9(DVSS) U1.G10(DVSS) U1.G11(DVSS) U1.G12(DVSS) U1.G13(DVSS) U1.H1(DVSS) U1.H6(DVSS) U1.H7(DVSS) U1.H8(DVSS) U1.H9(DVSS) U1.H10(DVSS) U1.H11(DVSS) U1.H14(DVSS) U1.H15(DVSS) U1.J7(DVSS) U1.J8(DVSS) U1.J9(DVSS) U1.J10(DVSS) U1.J11(DVSS) U1.J14(DVSS) U1.J17(DVSS) U1.K2(DVSS) U1.K4(DVSS) U1.K5(DVSS) U1.K6(DVSS) U1.K7(DVSS) U1.K8(DVSS) U1.K9(DVSS) U1.K10(DVSS) U1.K12(DVSS) U1.K13(DVSS) U1.L4(DVSS) U1.L5(DVSS) U1.L6(DVSS) U1.L7(DVSS) U1.L8(DVSS) U1.L9(DVSS) U1.L11(DVSS) U1.L12(DVSS) U1.L13(DVSS) U1.L14(DVSS) U1.L15(DVSS) U1.M4(DVSS) U1.M5(DVSS) U1.M9(DVSS) U1.M12(DVSS) U1.M13(DVSS) U1.M14(DVSS) U1.M17(DVSS) U1.N2(DVSS) U1.N3(DVSS) U1.N6(DVSS) U1.N7(DVSS) U1.N9(DVSS) U1.N10(DVSS) U1.N15(DVSS) U1.P2(DVSS) U1.P3(DVSS) U1.P4(DVSS) U1.P5(DVSS) U1.P8(DVSS) U1.P11(DVSS) U1.P14(DVSS) U1.R3(DVSS) U1.R8(DVSS) U1.R17(DVSS) U1.T1(DVSS) U1.T5(DVSS) U1.T9(DVSS) U1.T12(DVSS) U1.T15(DVSS) U1.U3(DVSS) U1.U6(DVSS) U1.U10(DVSS) U1.U13(DVSS) U1.U16(DVSS) U2.4(GND) U3.2(GND) U51.2(GND) U52.2(GND) U53.2(GND) U54.2(GND) U55.2(GND) U201.1(NC1) U201.3(NC2) U201.4(GND) U201.5(NC3) U201.9(NC4) U201.17(PGND2B) U201.22(PGND2A) U201.25(AGND) U201.26(NC5) U201.29(PGND1B) U201.34(PGND1A) U201.39(GND_IO) U201.41(E_PAD) U202.1(NC1) U202.3(NC2) U202.4(GND) U202.5(NC3) U202.9(NC4) U202.17(PGND2B) U202.22(PGND2A) U202.25(AGND) U202.26(NC5) U202.29(PGND1B) U202.34(PGND1A) U202.39(GND_IO) U202.41(E_PAD) U301.1(NC1) U301.3(NC2) U301.4(GND) U301.5(NC3) U301.9(NC4) U301.17(PGND2B) U301.22(PGND2A) U301.25(AGND) U301.26(NC5) U301.29(PGND1B) U301.34(PGND1A) U301.39(GND_IO) U301.41(E_PAD) U302.1(NC1) U302.3(NC2) U302.4(GND) U302.5(NC3) U302.9(NC4) U302.17(PGND2B) U302.22(PGND2A) U302.25(AGND) U302.26(NC5) U302.29(PGND1B) U302.34(PGND1A) U302.39(GND_IO) U302.41(E_PAD)
VCC5V: 5C13.2 5R5.1 C6.1 C7.1 C8.1 C9.2 C10.2 C13.1 C14.2 C51.1 C52.2 C57.1 C58.2 C68.1 C69.2 J814.1(VBUS) L1.2 R6.2 R10.2 R17.1 R18.1 R52.2 R329.1 R330.1 R334.1 R337.2 U3.5(IN) U51.5(IN) U52.5(IN) U53.5(IN)
VCC_3.3V: 2C22.2 2R18.1 2R19.1 2T15.1(TP) 4C4.2 4C5.1 4C8.2 4C17.2 4C18.2 4C49.2 4R6.2 4U5.1(NC_//_NC_//_VCC) 4U5.12(VCC1) 4U5.24(NC_//_NC_//_VCC2) 4U5.37(VCC2) 4U9.M6(VCC1) 4U9.N5(VCC2) 4U9.T10(VCC3) 4U9.U9(VCC4) 5C10.2 C22.1 C79.1 Q1.3(D) U1.A5(VDDIO_Z) U1.K15(AVDD33_USB) U55.1(VIN) U55.3(ON/OFF)
VDD_EE: 1R2.2 2C1.2 2C11.2 2C13.1 2C16.2 2C20.2 2R27.2 C60.1 C61.2 C62.1 C64.2 L52.2 R15.2 R53.2 R333.2 U1.F12(VDD_EE) U1.J3(VDD_EE) U1.J4(VDD_EE) U1.J5(VDD_EE) U1.J6(VDD_EE) U1.K11(VDD_EE)
VDDAO_3.3V: 2C5.2 2C15.2 2CON1.3 2D7.1 2R2.1 2R24.1 2R28.1 2U2.3(VIN) C16.1 C17.2 C18.1 C19.2 C21.1 C23.2 C101.2 C201.1 C230.1 C249.1 C250.2 C301.1 C330.1 L2.2 Q1.2(S) R8.2 R12.2 R62.1 R105.1 R214.2 R307.1 R314.2 R323.1 R335.1 R336.1 T129.1(TP) T316.1(TP) T319.1(TP) U1.D13(VDDIO_AO) U1.K14(VDDIO_A) U201.40(VDD_IO) U202.40(VDD_IO) U301.40(VDD_IO) U302.40(VDD_IO)
VDDCPU: 1R1.2 2C2.2 2C4.1 2C6.1 2C7.2 2C8.2 2C14.2 2C19.2 C54.1 C55.2 C56.1 C63.2 L51.2 R51.2 U1.F5(VDDCPU) U1.F6(VDDCPU) U1.G3(VDDCPU) U1.G4(VDDCPU) U1.G5(VDDCPU) U1.G6(VDDCPU) U1.H3(VDDCPU) U1.H4(VDDCPU) U1.H5(VDDCPU)
VDDCPU_EN: 2R2.2 R54.1 U1.C4(TESTN)
VDDCPU_PWM: 1R1.1 R56.2 U1.D3(GPIOAO_2//UART_CTS_AO_B//UART_CTS_AO_A//PWMAO_B)
VDDEE_PWM: 1R2.1 R58.2 U1.D4(GPIOAO_9//I2C_SDA_AO//PWMAO_D)
VDDIO_AO18: 2C10.2 2C12.2 2C17.1 2R3.2 2R29.2 3C1.2 5C9.2 5R20.1 C76.1 R106.1 U1.H12(AVDD18_SAR_PLL) U1.H13(VDD18_XTAL_IOVREF) U1.J12(AVDD18_DDRPLL) U1.J13(AVDD18_USB) U54.5(VOUT)
VDDIO_BOOT: 4C2.2 4C10.2 4C11.2 4C34.2 4C35.2 4C47.1 4C48.2 4R1.2 4R3.1 4R4.1 4R5.1 4R6.1 4R8.1 4R12.2 4R14.1 4R16.1 4U5.28((I/O10)_//_VCCQ) 4U5.34(NC_//_VCCQ_//_VCCQ) 4U5.45((I/O13)_//_VCCQ) 4U9.AA3(VCCQ4) 4U9.AA5(VCCQ5) 4U9.K6(VCCQ1) 4U9.W4(VCCQ2) 4U9.Y4(VCCQ3) U1.L3(VDDIO_BOOT)
VDDIO_X: C102.2 R105.2 R106.2 U1.C8(VDDIO_X)
VDDQ1.35V: 3C2.2 3C4.2 3C5.2 3C6.1 3C8.1 3C9.2 3C10.2 3C11.2 3C12.2 3C18.2 3C19.2 3C20.2 3C21.2 3C26.1 3C28.1 3C30.2 3C31.2 3C35.2 3C38.2 3C39.2 3C42.2 3C45.2 3C58.2 3C62.2 3R8.2 3R19.2 3U1.A1(VDDQ) 3U1.A8(VDDQ) 3U1.B2(VDD) 3U1.C1(VDDQ) 3U1.C9(VDDQ) 3U1.D2(VDDQ) 3U1.D9(VDD) 3U1.E9(VDDQ) 3U1.F1(VDDQ) 3U1.G7(VDD) 3U1.H2(VDDQ) 3U1.H9(VDDQ) 3U1.K2(VDD) 3U1.K8(VDD) 3U1.N1(VDD) 3U1.N9(VDD) 3U1.R1(VDD) 3U1.R9(VDD) C71.1 C72.2 C73.1 C74.2 L53.2 R61.2 U1.M6(VDDQ) U1.M7(VDDQ) U1.M8(VDDQ) U1.M10(VDDQ) U1.M11(VDDQ) U1.N4(VDDQ) U1.N5(VDDQ)
ACTIVE_STBY: R219.1 R320.1 U1.B11(GPIOX_19//I2C_SDA_C//UART_CTS_EE_B//SPI_CLK_B//PWM_B)
AMP_RESET: 5R74.2 R215.1 R315.1 T317.1(TP)
AMP_SCL: 2R24.2 5R66.2 R209.1 U1.A16(GPIOAO_10//I2C_SLAVE_SCK_AO//I2C_SCK_AO)
AMP_SCL_DEV: R209.2 R238.1 R309.1 T306.1(TP)
AMP_SDA: 2R28.2 5R65.2 R210.1 U1.B15(GPIOAO_11//I2C_SLAVE_SDA_AO//I2C_SDA_AO)
AMP_SDA_DEV: R210.2 R239.1 R310.1 T305.1(TP)
BCLK: 5R68.1 J813.11
CPU_RESET: 2R14.1 2U2.2(RESET_n) R240.1 R338.1 U1.A12(RESETN)
CTRL_A113X: 5R75.2 5R76.1 5R77.1
DATA: 5R69.1 J813.12
DDR3_A0: 3U1.N3(A0) U1.R12(A0)
DDR3_A1: 3U1.P7(A1) U1.U15(A1)
DDR3_A2: 3U1.P3(A2) U1.P16(A2)
DDR3_A3: 3U1.N2(A3) U1.U17(A3)
DDR3_A4: 3U1.P8(A4) U1.R11(A4)
DDR3_A5: 3U1.P2(A5) U1.T14(A5)
DDR3_A6: 3U1.R8(A6) U1.P12(A6)
DDR3_A7: 3U1.R2(A7) U1.U14(A7)
DDR3_A8: 3U1.T8(A8) U1.P13(A8)
DDR3_A9: 3U1.R3(A9) U1.T16(A9)
DDR3_A10: 3U1.L7(A10) U1.R10(A10)
DDR3_A11: 3U1.R7(A11) U1.P17(A11)
DDR3_A12: 3U1.N7(A12) U1.T17(A12)
DDR3_A13: 3U1.T3(A13) U1.R15(A13)
DDR3_A14: 3U1.T7(A14) U1.R14(A14(A14/WE_N))
DDR3_A15: 3U1.M7(A15) U1.T13(A15(A15/CAS_N))
DDR3_BA0: 3U1.M2(BA0) U1.N16(BA_0)
DDR3_BA1: 3U1.N8(BA1) U1.U12(BA_1)
DDR3_BA2: 3U1.M3(BA2) U1.M16(BA_2(BG0))
DDR3_CAS: 3U1.K3(/CAS) U1.P15(CAS_N(ACT_N))
DDR3_CKE0: 3U1.K9(CKE) U1.P10(CKE0)
DDR3_CLKn: 3C7.1 3R2.2 3U1.K7(/CK) U1.T10(CKN)
DDR3_CLKp: 3C7.2 3R2.1 3U1.J7(CK) U1.U9(CKP)
DDR3_DQ0: 3U1.A2(UDQ5) U1.T2(DQ0)
DDR3_DQ1: 3U1.C2(UDQ3) U1.T3(DQ1)
DDR3_DQ2: 3U1.A7(UDQ4) U1.P6(DQ2)
DDR3_DQ3: 3U1.D7(UDQ0) U1.U7(DQ3)
DDR3_DQ4: 3U1.A3(UDQ7) U1.U1(DQ4)
DDR3_DQ5: 3U1.C3(UDQ1) U1.U2(DQ5)
DDR3_DQ6: 3U1.B8(UDQ6) U1.R6(DQ6)
DDR3_DQ7: 3U1.C8(UDQ2) U1.T7(DQ7)
DDR3_DQ8: 3U1.H7(LDQ7) U1.T8(DQ8)
DDR3_DQ9: 3U1.F2(LDQ2) U1.R2(DQ9)
DDR3_DQ10: 3U1.H8(LDQ5) U1.R9(DQ10)
DDR3_DQ11: 3U1.E3(LDQ0) U1.R4(DQ11)
DDR3_DQ12: 3U1.F8(LDQ3) U1.R7(DQ12)
DDR3_DQ13: 3U1.H3(LDQ4) U1.P1(DQ13)
DDR3_DQ14: 3U1.F7(LDQ1) U1.P9(DQ14)
DDR3_DQ15: 3U1.G2(LDQ6) U1.R1(DQ15)
DDR3_DQM0: 3U1.D3(UDM) U1.R5(DQM0)
DDR3_DQM1: 3U1.E7(LDM) U1.P7(DQM1)
DDR3_DQSn0: 3U1.B7(/UDQS) U1.T6(DQSN_0)
DDR3_DQSn1: 3U1.G3(/LDQS) U1.T4(DQSN_1)
DDR3_DQSp0: 3U1.C7(UDQS) U1.U5(DQSP_0)
DDR3_DQSp1: 3U1.F3(LDQS) U1.U4(DQSP_1)
DDR3_nCS0: 3U1.L2(/CS) U1.U11(CS0_N)
DDR3_ODT0: 3U1.K1(ODT) U1.R16(ODT0)
DDR3_RAS: 3U1.J3(/RAS) U1.T11(RAS_N(A16/RAS_N))
DDR3_RST: 3C46.2 3R8.1 3U1.T2(/RST) U1.M15(RST_N)
DDR3_WE: 3U1.L3(/WE) U1.R13(WE_N(BG1))
eMMC_1.8V: 4R5.2 C77.1 U55.5(VOUT)
GPIOX_16: T125.1(TP) U1.D10(GPIOX_16//I2C_SCK_B//UART_TX_EE_B//SPI_SS0_B//PWM_D)
GPIOX_17: T126.1(TP) U1.D8(GPIOX_17//I2C_SDA_B//UART_RX_EE_B//SPI_MOSI_B//PWM_C)
GPIOX_18: T127.1(TP) U1.C10(GPIOX_18//I2C_SCK_C//UART_RTS_EE_B//SPI_MISO_B//PWM_A)
GPIOZ_10: 2T3.1(TP) U1.E2(GPIOZ_10)
HW_VS: 2R3.1 2R15.2 U1.D15(SARADC_CH1)
I2SIN_BCLK_C: 5R68.2 U1.G15(GPIOA_8//TDMB_SCLK//TDMB_SLV_SCLK)
I2SIN_DATA_C: 5R69.2 R103.2 R104.2
I2SIN_LRCK_C: 5R67.2 U1.F17(GPIOA_9//TDMB_FS//TDMB_SLV_FS)
I2SIN_MCLK_B: 5R70.2 R102.2
I2SO_BCLK: C103.2 R107.2 R227.1 R229.1 R325.1 R327.1 T309.1(TP)
I2SO_DATA0: C105.2 R109.2 R225.2 R231.2 U201.7(SDATA) U301.7(SDATA)
I2SO_DATA1: C106.2 R110.2 R226.2 R231.1 U202.7(SDATA) U302.7(SDATA)
I2SO_LRCLK: C104.2 R108.2 R228.1 R230.1 R326.1 R328.1 T307.1(TP)
I2SO_MCLK_A: R101.2 T101.1(TP)
IR_IN: 2T6.1(TP) U1.B14(GPIOAO_6//IR_REMOTE_INPUT)
IR_OUT: 2T5.1(TP) U1.B13(GPIOAO_7//IR_REMOTE_OUT//JTAG_TMS)
LCD_BL_EN: 2T21.1(TP) U1.B1(GPIOZ_5//SPI_SS2_A//PWM_A//SPDIF_OUT)
LCD_BL_PWM: 2T22.1(TP) U1.C7(GPIOZ_4//SPI_SS1_A//PWM_B//SPDIF_IN)
LCD_RESET: 2T24.1(TP) U1.C2(GPIOZ_6//I2C_SCK_A//UART_CTS_AO_B)
LINE_OUT_DET: 2T23.1(TP) U1.D2(GPIOZ_7//I2C_SDA_A//UART_RTS_AO_B)
Linux_RX: 2D4.1 2R1.2 U1.B12(GPIOAO_1//UART_RX_AO_A)
Linux_TX: 2D3.1 2R16.2 U1.A13(GPIOAO_0//UART_TX_AO_A)
LRCK: 5R67.1 J813.10
MCLK: 5R70.1 J813.14
MDDR3_VREF1: 3C27.2 3C40.2 3R19.1 3R20.2 3U1.H1(VREFDQ) 3U1.M8(VREFCA)
NAND_ALE: 4U5.17(ALE) 4U9.U5(RST_n) U1.M1(BOOT_9//EMMC_RST//NAND_ALE//NOR_WPN)
NAND_CLE: 4R14.2 4U5.16(CLE) 4U9.W5(CMD) U1.L2(BOOT_10//EMMC_CMD//NAND_CLE)
NAND_CS1: 4C3.2 4R1.1 4R11.1 4R11.2 4U5.9(~{CE}1) 4U9.W6(CLK) U1.L1(BOOT_8//EMMC_CLK//NAND_CE0)
NAND_D0: 4R16.2 4R19.1 4R19.2 4U5.29(I/O0) 4U9.H3(DATA0) U1.F2(BOOT_0//EMMC_D0)
NAND_D1: 4R20.1 4R20.2 4U5.30(I/O1) 4U9.H4(DATA1) U1.F1(BOOT_1//EMMC_D1)
NAND_D2: 4R21.1 4R21.2 4U5.31(I/O2) 4U9.H5(DATA2) U1.G1(BOOT_2//EMMC_D2)
NAND_D3: 4R22.1 4R22.2 4U5.32(I/O3) 4U9.J2(DATA3) U1.G2(BOOT_3//EMMC_D3//NOR_HOLDN)
NAND_D4: 4R23.1 4R23.2 4R52.2 4U5.41(I/O4) 4U9.J3(DATA4) U1.H2(BOOT_4//EMMC_D4//NOR_D//POC0)
NAND_D5: 4R10.2 4R24.1 4R24.2 4U5.42(I/O5) 4U9.J4(DATA5) U1.J1(BOOT_5//EMMC_D5//NOR_Q//POC1)
NAND_D6: 4R13.2 4R25.1 4R25.2 4U5.43(I/O6) 4U9.J5(DATA6) U1.J2(BOOT_6//EMMC_D6//NOR_C//POC2)
NAND_D7: 4R2.2 4R26.1 4R26.2 4U5.44(I/O7) 4U9.J6(DATA7) U1.K1(BOOT_7//EMMC_D7//POC3)
NAND_nR/B: 4R9.1 4R12.1 4R17.1 4U5.6(R/~{BY}2) 4U5.7(R/~{BY}1) U1.K3(BOOT_13//EMMC_DS//NAND_RB)
NAND_nRE: 4R18.1 4R18.2 4U5.8(~{RE}_//_~{RE}(W/~{R})_//_~{RE}) U1.M2(BOOT_12//NAND_REN_WR)
NAND_nWE: 4R15.1 4R15.2 4U5.18(~{WE}_//_~{WE}(CLK)_//_~{WE}) U1.N1(BOOT_11//NAND_WEN_CLK)
NAND_PSL: 4R3.2 4U5.39(NC_//_VCCQ_//_PSL)
NAND_VSP: 4R7.2 4R8.2 4U5.38(NC_//_VSP1_//_VCCQ)
nPWM_OFF1: R219.2 U201.12(\\~{FAUL}T) U202.12(\\~{FAUL}T)
nPWM_OFF2: R320.2 U301.12(\\~{FAUL}T) U302.12(\\~{FAUL}T)
nRESET_AMP: R216.1 R316.1 U1.B6(GPIOX_20//PWM_A)
nRST_AMP1: C204.2 C226.2 R215.2 R216.2 R240.2 U201.36(\\~{RESE}T) U202.36(\\~{RESE}T)
nRST_AMP2: C304.2 C326.2 R315.2 R316.2 R338.2 U301.36(\\~{RESE}T) U302.36(\\~{RESE}T)
PDM_DCLK: T102.1(TP) U1.E16(GPIOA_14//PDM_DCLK//CLKSYN_IN//PWM_A)
PDM_DIN0: T103.1(TP) U1.E17(GPIOA_15//PDM_DIN0//PWM_B)
PDM_DIN1: T104.1(TP) U1.D16(GPIOA_16//PDM_DIN1//PWM_C)
PDM_DIN2: T105.1(TP) U1.D17(GPIOA_17//PDM_DIN2//I2C_SDA_C//ETH_MDIO)
PDM_DIN3: T106.1(TP) U1.C17(GPIOA_18//PDM_DIN3//I2C_SCK_C//ETH_MDC)
POWERSTB: R12.1 R13.1 U1.C12(GPIOAO_12//CLK12_24//PWMAO_B)
PVREF: 3T1.1(TP) U1.N11(PVREF)
PWR_24V: C1.1 C2.1 C3.1 C4.1 C30.1 C205.1 C206.1 C223.1 C224.1 C231.1 C248.1 C255.1 C256.1 C257.1 C258.1 C305.1 C306.1 C323.1 C324.1 C331.1 C348.1 C353.1 C354.1 C355.1 C356.1 R1.2 T1.1 U2.2(VIN) U201.19(PVDD2B) U201.20(PVDD2A) U201.31(PVDD1B) U201.32(PVDD1A) U202.19(PVDD2B) U202.20(PVDD2A) U202.31(PVDD1B) U202.32(PVDD1A) U301.19(PVDD2B) U301.20(PVDD2A) U301.31(PVDD1B) U301.32(PVDD1A) U302.19(PVDD2B) U302.20(PVDD2A) U302.31(PVDD1B) U302.32(PVDD1A)
RMII_MDC: T322.1(TP) U1.A11(GPIOX_22//ETH_MDC)
RMII_MDIO: T323.1(TP) U1.A8(GPIOX_21//ETH_MDIO)
RMII_RXCLK: T325.1(TP) U1.B7(GPIOX_12//TDMA_SCLK//TDMA_SLV_SCLK//RMII_RX_CLK)
RMII_RXD0: T327.1(TP) U1.B8(GPIOX_13//TDMA_FS//TDMA_SLV_FS//RMII_RXD0)
RMII_RXD1: T326.1(TP) U1.A6(GPIOX_14//TDMA_DIN0//TDMA_DOUT0//RMII_RXD1)
RMII_RXDV: T324.1(TP) U1.A7(GPIOX_15//TDMA_DOUT0//TDMA_DOUT1//TDMA_DIN1//RMII_RXDV)
RMII_TXD0: T328.1(TP) U1.A10(GPIOX_8//UART_TX_EE_A//RMII_TXD0)
RMII_TXD1: T331.1(TP) U1.C9(GPIOX_9//UART_RX_EE_A//RMII_TXD1)
RMII_TXEN: T329.1(TP) U1.B9(GPIOX_10//UART_CTS_EE_A//PWM_C//RMII_TXEN)
SCL: 5R66.1 J813.8
SCL_AMP1: C222.2 C246.2 R211.2 R238.2 U201.11(SCL) U202.11(SCL)
SCL_AMP2: C322.2 C346.2 R309.2 R311.2 U301.11(SCL) U302.11(SCL)
SDA: 5R65.1 J813.7
SDA_AMP1: C217.2 C241.2 R212.2 R239.2 U201.10(SDA) U202.10(SDA)
SDA_AMP2: C317.2 C341.2 R310.2 R312.2 U301.10(SDA) U302.10(SDA)
SPDIF_IN: T107.1(TP) U1.E14(GPIOA_19//SPDIF_IN//SPDIF_OUT//PDM_DCLK//I2C_SDA_D)
SPDIF_OUT: T108.1(TP) U1.C16(GPIOA_20//SPDIF_OUT//SPDIF_IN//CLKSYN_IN//I2C_SCK_D)
SPI_CLK: 2T16.1(TP) U1.C6(GPIOZ_0//SPI_CLK_A//UART_RTS_EE_B)
SPI_MISO: 2T19.1(TP) U1.D6(GPIOZ_2//SPI_MISO_A//UART_TX_EE_B)
SPI_MOSI: 2T18.1(TP) U1.C5(GPIOZ_1//SPI_MOSI_A//UART_CTS_EE_B)
SPI_SS0: 2T20.1(TP) U1.C1(GPIOZ_3//SPI_SS0_A//UART_RX_EE_B)
SPK_I2C_SCK: 2R18.2 2T26.1(TP) R211.1 R311.1 U1.E3(GPIOZ_8//I2C_SCK_B//UART_TX_AO_B)
SPK_I2C_SDA: 2R19.2 2T27.1(TP) R212.1 R312.1 U1.D1(GPIOZ_9//I2C_SDA_B//UART_RX_AO_B)
SPK_RST: 2T8.1(TP) U1.C15(GPIOAO_4//UART_TX_AO_B//I2C_SCK_AO//JTAG_TDO)
STANDBY_A113X: 5R77.2 U1.C13(GPIOAO_8//CLK_32K_IN//I2C_SCK_AO//PWMAO_C)
SYS_LED: 2R8.2 U1.A15(GPIOAO_3//UART_RTS_AO_B//UART_RTS_AO_A//PWMAO_A//JTAG_TDI)
USB_PWR_EN: 2T7.1(TP) U1.C11(GPIOAO_5//UART_RX_AO_B//I2C_SDA_AO//JTAG_CLK)
USB_TXRTUNE: 5R64.1 U1.J15(USB_TXRTUNE)
USBOTG_A_DM: 5D12.1 5R71.2 5R84.2 U1.L16(USB_DM)
USBOTG_A_DP: 5D11.1 5R72.2 5R85.2 U1.L17(USB_DP)
USBOTG_A_ID: 5C3.2 5R20.2 5R76.2 5R78.1 5R83.2 U1.K17(USB_ID)
USBOTG_A_VBUS: 5C11.2 5R5.2 U1.K16(USB_VBUS)
WPn: 4C9.2 4R4.2 4U5.19(~{WP})
N21450221: C23.1 Q1.1(G) R13.2
N21455517: 2R27.1 U1.F13(VDDAO_0V9)
N21455804: 2R29.1 U1.E15(SARADC_CH0)
N21455846: 2Q1.3(COLLECTOR) 2R12.2
N21455854: 2D7.2 2R12.1
N21456017: 2T29.1(TP) U1.D11(GPIOAO_13//CLK25_EE//GEN_CLK_AO//PWMAO_C//GEN_CLK_EE)
N21456060: 2C3.2 2R5.1 2Y2.1 U1.B16(SYS_OSCIN)
N21456068: 2R10.2 U1.A17(SYS_OSCOUT)
N21456125: 2C9.2 2R5.2 2R10.1 2Y2.3
N21456352: 2CON1.4 2R1.1
N21456391: 2CON1.2 2R16.1
N21464427: 3R6.2 U1.N8(PZQ)
N21467829: 4T25.1(TP) U1.M3(BOOT_14//NOR_CS)
N21468142: 4K2.3 4K2.4 4R10.1
N21476089: R101.1 U1.J16(GPIOA_0//MCLK_C//CLKSYN_IN//PWM_VS)
N21476146: R102.1 U1.H17(GPIOA_1//MCLK_B//SPDIF_IN//SPDIF_OUT//CLKSYN_IN)
N21492258: C53.2 L51.1 U51.6(LX)
N21492341: C65.2 R54.2 R337.1 U51.4(EN)
N21492347: C53.1 U51.1(BS)
N21492451: C63.1 R51.1 R55.1 R59.2 U51.3(FB)
N21492734: C66.2 R55.2 R56.1
N21494202: C78.1 R334.2 R335.2 U54.1(VIN)
N21494218: R331.1 R336.2 U54.3(ON/OFF)
N21499562: C59.2 L52.1 U52.6(LX)
N21499612: R52.1 U52.4(EN)
N21499616: C59.1 U52.1(BS)
N21499652: C64.1 R53.1 R57.1 R60.2 U52.3(FB)
N21499757: C67.2 R57.2 R58.1
N21500929: C70.2 L53.1 U53.6(LX)
N21500979: C75.2 R62.2 U53.4(EN)
N21500983: C70.1 U53.1(BS)
N21501019: C74.1 R61.1 R63.2 U53.3(FB)
N21504673: C5.1 U2.5(BST)
N21504675: C5.2 L1.1 U2.3(SW)
N21504709: R20.1 U2.8(FB)
N21504737: C10.1 R10.1 R11.2 R20.2
N21506095: C15.2 L2.1 U3.6(LX)
N21506141: C20.2 R6.1 R7.2 R19.1 U3.4(EN)
N21506145: C15.1 U3.1(BS)
N21506181: C19.1 R8.1 R9.2 U3.3(FB)
N21534101: 3R10.2 3U1.L8(ZQ)
N21597998: 2Q1.1(BASE) 2R8.1
N21714583: C202.2 C210.1 L201.1 L211.1 R202.2 R203.1 U201.30(OUT1B) U201.33(OUT1A)
N21714609: C251.2 R227.2 U201.38(BCK)
N21714673: C203.2 R202.1
N21714680: C202.1 U201.35(BST1A)
N21714717: R201.1 U201.37(AD)
N21714779: C207.2 R203.2
N21714803: C208.2 U201.2(VDD_PLL)
N21714864: C209.1 C213.1 D201.1 J803.1 L201.2 L211.2 R204.2
N21714950: C210.2 U201.28(BST1B)
N21714966: C211.1 U201.27(VDR1)
N21715014: C218.1 U201.6(DVDD)
N21715038: C214.1 U201.24(VDR2)
N21715052: C213.2 C216.2 D202.1 J803.2 L202.2 L212.2 R205.1
N21715056: C215.2 U201.23(BST2A)
N21715058: C215.1 C220.1 L202.1 L212.1 R206.2 R208.1 U201.18(OUT2B) U201.21(OUT2A)
N21715192: C219.2 R206.1
N21715198: T201.1(TP) U201.13(MONITOR_0)
N21715200: R207.2 U201.14(MONITOR_1)
N21715202: T202.1(TP) U201.15(MONITOR_2)
N21715204: C220.2 U201.16(BST2B)
N21715315: C221.2 R208.2
N21715405: C233.1 C237.1 D203.1 J803.4 L203.2 L213.2 R220.2
N21715413: C237.2 C240.2 D204.1 J803.3 L204.2 L214.2 R221.1
N21715441: C225.2 C234.1 L203.1 L213.1 R213.2 R217.1 U202.30(OUT1B) U202.33(OUT1A)
N21715461: C253.2 R229.2 U202.38(BCK)
N21715523: C228.2 R213.1
N21715527: C225.1 U202.35(BST1A)
N21715561: R214.1 U202.37(AD)
N21715623: C229.2 R217.2
N21715647: C232.2 U202.2(VDD_PLL)
N21715792: C234.2 U202.28(BST1B)
N21715808: C235.1 U202.27(VDR1)
N21715856: C242.1 U202.6(DVDD)
N21715880: C238.1 U202.24(VDR2)
N21715898: C239.2 U202.23(BST2A)
N21715900: C239.1 C244.1 L204.1 L214.1 R222.2 R224.1 U202.18(OUT2B) U202.21(OUT2A)
N21716032: C243.2 R222.1
N21716038: T203.1(TP) U202.13(MONITOR_0)
N21716040: R223.2 U202.14(MONITOR_1)
N21716042: T204.1(TP) U202.15(MONITOR_2)
N21716044: C244.2 U202.16(BST2B)
N21716155: C245.2 R224.2
N21722582: C302.2 C310.1 L301.1 L311.1 R302.2 R303.1 U301.30(OUT1B) U301.33(OUT1A)
N21722605: C349.2 R325.2 U301.38(BCK)
N21722669: C303.2 R302.1
N21722673: C302.1 U301.35(BST1A)
N21722707: R301.1 U301.37(AD)
N21722769: C307.2 R303.2
N21722793: C308.2 U301.2(VDD_PLL)
N21722854: C309.1 C313.1 D301.1 J804.1 L301.2 L311.2 R304.2
N21722936: C310.2 U301.28(BST1B)
N21722954: C311.1 U301.27(VDR1)
N21722998: C318.1 U301.6(DVDD)
N21723019: C314.1 U301.24(VDR2)
N21723033: C313.2 C316.2 D302.1 J804.2 L302.2 L312.2 R305.1
N21723038: C315.2 U301.23(BST2A)
N21723040: C315.1 C320.1 L302.1 L312.1 R306.2 R308.1 U301.18(OUT2B) U301.21(OUT2A)
N21723161: C319.2 R306.1
N21723167: T301.1(TP) U301.13(MONITOR_0)
N21723169: R307.2 U301.14(MONITOR_1)
N21723171: T302.1(TP) U301.15(MONITOR_2)
N21723173: C320.2 U301.16(BST2B)
N21723285: C321.2 R308.2
N21723451: C333.1 C337.1 D303.1 J804.4 L303.2 L313.2 R319.2
N21723475: C337.2 C340.2 D304.1 J804.3 L304.2 L314.2 R321.1
N21723494: C325.2 C334.1 L303.1 L313.1 R313.2 R317.1 U302.30(OUT1B) U302.33(OUT1A)
N21723515: C351.2 R327.2 U302.38(BCK)
N21723601: C328.2 R313.1
N21723605: C325.1 U302.35(BST1A)
N21723639: R314.1 U302.37(AD)
N21723713: C329.2 R317.2
N21723762: C332.2 U302.2(VDD_PLL)
N21723903: C334.2 U302.28(BST1B)
N21723921: C335.1 U302.27(VDR1)
N21723965: C342.1 U302.6(DVDD)
N21723986: C338.1 U302.24(VDR2)
N21724005: C339.2 U302.23(BST2A)
N21724007: C339.1 C344.1 L304.1 L314.1 R322.2 R324.1 U302.18(OUT2B) U302.21(OUT2A)
N21724126: C343.2 R322.1
N21724132: T303.1(TP) U302.13(MONITOR_0)
N21724134: R323.2 U302.14(MONITOR_1)
N21724136: T304.1(TP) U302.15(MONITOR_2)
N21724138: C344.2 U302.16(BST2B)
N21724244: C345.2 R324.2
N21727322: J812.2 T1.4
N21727332: J812.1 T1.3
N21729503: C11.2 U2.7(SS)
N21735247: 4C26.2 4U9.K2(VDDI)
N21735401: 4R17.2 4U9.R5(Data_Strobe)
N21775203: 5R71.1 J813.1
N21775223: 5R72.1 J813.2
N21775243: 5R73.1 J813.4
N21775263: 5R74.1 J813.5
N21775283: 5R75.1 J813.6
N21778072: T109.1(TP) U1.A4(GPIOX_0//SDIO_D0//JTAG_TDO)
N21778081: T110.1(TP) U1.B5(GPIOX_1//SDIO_D1//JTAG_TDI)
N21778090: T111.1(TP) U1.B2(GPIOX_2//SDIO_D2//UART_RX_AO_A)
N21778099: T112.1(TP) U1.A2(GPIOX_3//SDIO_D3//UART_TX_AO_A)
N21778148: T113.1(TP) U1.A3(GPIOX_4//SDIO_CLK//JTAG_CLK)
N21778157: T114.1(TP) U1.B3(GPIOX_5//SDIO_CMD//JTAG_TMS)
N21778166: T115.1(TP) U1.A1(GPIOX_6)
N21778175: T116.1(TP) U1.C3(GPIOX_7)
N21778255: T120.1(TP) U1.B10(GPIOX_11//UART_RTS_EE_A//PWM_D)
N21800110: R225.1 R226.1 T310.1(TP)
N21860313: C252.2 R228.2 U201.8(WCK)
N21864534: C254.2 R230.2 U202.8(WCK)
N21877006: C350.2 R326.2 U301.8(WCK)
N21880362: C352.2 R328.2 U302.8(WCK)
N21888872: Q3.3(COLLECTOR) R16.2 R17.2
N21888995: Q2.3(COLLECTOR) R18.2 R19.2
N21888998: Q2.1(BASE) R16.1
N21889394: Q3.1(BASE) R15.1
N21890397: Q4.3(COLLECTOR) R329.2 R332.2
N21890399: Q5.3(COLLECTOR) R330.2 R331.2
N21890429: Q5.1(BASE) R332.1
N21890459: Q4.1(BASE) R333.1
N21892603: R103.1 U1.F16(GPIOA_10//TDMB_DOUT0//TDMB_DIN0)
N21892620: R104.1 U1.F15(GPIOA_11//TDMB_DOUT1//TDMB_DIN1//SPDIF_OUT)
N21892674: R107.1 U1.H16(GPIOA_2//TDMC_SCLK//TDMC_SLV_SCLK//SPI_MOSI_B)
N21892682: R108.1 U1.G17(GPIOA_3//TDMC_FS//TDMC_SLV_FS//SPI_MISO_B)
N21892690: R109.1 U1.G16(GPIOA_4//TDMC_DOUT0//TDMC_DIN0//SPI_CLK_B)
N21892698: R110.1 U1.G14(GPIOA_5//TDMC_DOUT1//TDMC_DIN1//SPI_SS0_B)
N22017810: 5R84.1 J814.2(D-)
N22017884: 5R83.1 J814.4(ID)
N22060831: 5R85.1 J814.3(D+)

Not connected (* = marked no-connect by the designer): 3U1 J1(NC/ODT1)* J9(NC/CKE1)* L1(NC/CS1)* L9(NC/ZQ1)*; 4U5 3(NC//VDDi//NC)* 4(NC_//_R/~{BY}4_//_NC)* 5(NC_//_NC_//_R/~{BY}3_//_NC)* 10(~{CE}2)* 11(NC2)* 14(NC_//_~{CE}3_//_NC)* 15(NC_//_~{CE}4_//_NC)* 20(NC_//_VSP3_//_NC)* 21(NC//ENi//NC)* 22(NC//ENo//NC)* 26((I/O8)_//_NC)* 35(NC_//_VSP2(DQS)_//_DQS)* 47((I/O15))*; 4U9 A4(NC1)* A6(NC2)* A9(NC3)* A11(NC4)* AA1(NC140)* AA2(NC122)* AA7(NC123)* AA8(NC124)* AA9(NC125)* AA10(VFS7)* AA11(NC127)* AA12(NC128)* AA13(NC129)* AA14(NC130)* AE1(NC131)* AE14(NC132)* AG2(NC133)* AG13(NC134)* AH4(NC135)* AH6(NC136)* AH9(NC137)* AH11(NC138)* B2(NC5)* B13(NC6)* D1(NC7)* D14(NC8)* H1(NC9)* H2(NC141)* H7(RFU1)* H8(NC13)* H9(NC14)* H10(NC15)* H11(NC16)* H12(NC17)* H13(NC18)* H14(NC19)* J1(NC143)* J7(NC21)* J8(NC22)* J9(NC23)* J10(NC24)* J11(NC25)* J12(NC26)* J13(NC27)* J14(NC28)* K1(NC29)* K3(NC146)* K5(NC144)* K7(NC32)* K8(NC33)* K9(NC34)* K10(NC35)* K11(NC36)* K12(NC37)* K13(NC38)* K14(NC39)* L1(NC40)* L2(NC41)* L3(NC42)* L4(NC43)* L12(NC139)* L13(NC44)* L14(NC45)* M1(NC46)* M2(NC47)* M3(NC48)* M5(NC49)* M8(VFS1)* M9(VFS2)* M10(VFS3)* M12(NC53)* M13(NC54)* M14(NC55)* N1(NC56)* N2(NC57)* N3(NC58)* N10(VFS4)* N12(NC60)* N13(NC61)* N14(NC62)* P1(NC63)* P2(NC64)* P3(NC65)* P10(VFS5)* P12(NC67)* P13(NC68)* P14(NC69)* R1(NC70)* R2(NC71)* R3(NC72)* R12(NC74)* R13(NC75)* R14(NC76)* T1(NC77)* T2(NC78)* T3(NC79)* T12(NC81)* T13(NC82)* T14(NC83)* U1(NC84)* U2(NC85)* U3(NC86)* U6(NC88)* U7(NC89)* U10(VFS6)* U12(NC91)* U13(NC92)* U14(NC93)* V1(NC94)* V2(NC95)* V3(NC96)* V12(NC97)* V13(NC98)* V14(NC99)* W1(NC100)* W2(NC101)* W3(NC102)* W7(NC103)* W8(NC104)* W9(NC105)* W10(NC106)* W11(NC107)* W12(NC108)* W13(NC109)* W14(NC110)* Y1(NC145)* Y3(NC112)* Y6(NC113)* Y7(NC114)* Y8(NC115)* Y9(NC116)* Y10(NC117)* Y11(NC118)* Y12(NC119)* Y13(NC120)* Y14(NC121)*; T330 1(TP)*; U1 N12(ODT1)* N13(CKE1)* N14(CS1_N)*; U2 1(PG)*; U54 4(NC)*; U55 4(NC)*

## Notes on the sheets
sheet 1
- * DVT3
- Design Max: 3A
- * REV1.0
- Active High
  (Default Low)
- * DVT3
- * DVT3
- GPIOAO_12
- 5V to VDDAO_3.3V
- Design Max: 2A
- L= > POWER_On(default)
- H= > POWER_OFF
sheet 2
- For Linux Debug
- HW ID
- 0.1
- 0.2
- 0.3
- 1.0
- 1.1
- ADC Data
- 248
- 334
- 420
- 512
- 603
- PUILL-UP
- 75K
- 58K
- 56K
- 47K
- 39K
- * REV1.0
- PUILL-DOWN
- 24K
- 33K
- 39K
- 47K
- 56K
- VERSION
- O
- V3
- mark signal name on PCB
- * REV1.0
- 2R23,2R24 for Charge Option
- * REV1.0
- No Pull Down
- CPU Reset
- * REV1.0
- SPI & I2C IO Debug
- System LED
- Logic
- LED function
- SYS_LED=1
- System running:
  green LED
- TP -TP: 2.0mm
  Bottom Layer
sheet 4
- Standby power supply
- DC-DC
- DC-DC
- Power
  24V
- 12V 4A
- INPUT4.5V-40V
- VCC5V
- INPUT4.5V-18V
- VDDAO_3.3V
- PMOS
- VCC_3.3V
- INPUT2.5V-5.5V
- LDO
- eMMC_1.8V
- MP2338 (3A)
- TMI3452S (2A)
- WPM3401 (3A）
- TMI6050-18(600mA)
- GPIOAO_13  5V_EN
- VDD33_AO Pin  10mA
- GPIOAO_12  POWERSTB
- VDDIO_X Pin(Optional)
- AVDD33_USB Pin
- LED Power  3mA
- VDDIO_BOOT Pin
- VDDIO_A Pin
- VDDIO_Y Pin (Optional)
- AMP 3.3V Power
- eMMC& NAND&SPI Nor  VCC Power
- Audio VCC_3.3V Power
- VDDIO_AO18
- VDDIO_X Pin 12mA
- INPUT2.5V-5.5V
- LDO
- TMI6050-18(500mA)
- VDD18_XTAL_IOVREF Pin  10mA
  (100mA peak when writing eFuse)
- AVDD18_DDRPLL Pin 30mA
- AVDD18_USB  Pin 20mA
- AVDD18_SAR_PLL Pin  40mA
- DC-DC
- INPUT4.5V-18V
- VDD_EE
- VDD_EE Pin  500mA
- TMI3452S (2A)
- VDDAO_0V9  Pin 20mA
- DC-DC
- INPUT4.5V-18V
- VDDQ1.35V  Max:600mA
- TMI3452S (2A)
- VDDAO_3.3V
- DC-DC
- INPUT4.5V-18V
- VDDCPU  1600mA
- TMI3452S (2A)
- TESTN VDDCPU_EN
sheet 5
- DDR3L
sheet 6
- * DVT3
- Design Max: 2A
- * DVT3
- Design Max: 2A
- 0.86V - 1.14V
- 0.81V - 1.09V
- GPIOAO_2(Hi-Z)
  Value is only for:
  1. 3.3V VDDIO
  2. 0.6V FB DC-DC
- GPIOAO_9(Hi-Z)
  Value is only for:
  1. 3.3V VDDIO
  2. 0.6V FB DC-DC
- * DVT3
- Design Max: 2A
- Note: Select fast power on
  LDO to make sure VDDAO_1.8V
   ramps up with VDDAO_3.3V at same time
- DDR3 1.5V : 1R46=100K_1%   1R47=66.5K_1%
- DDR3L  1.35V: 1R46=120K_1%  1R47=95.3K_1%
- DDR4  1.2V : 1R46=100K_1%   1R47=100K_1%
- For Fix SPK and MIC PCB Board
sheet 7
- * REV1.0
- *REV1.0
sheet 8
- eMMC/iNAND
- PCB Decal:169pin balls Type(BGA)
- VCC = 2.7 -3.6V
- VDDIO_BOOT
- MXIC SCL NAND need
  to Pull Donw 38 pin
- Do not route over RFU & VFS pins
- Note:
     eMMC   :4R9 ->10K, 4R12-> NC
  NAND Flash: 4R9 ->NC, 4R12->
  10K(default)
- CLOSE TO NAND
- Power ON Config
- NAND(TSOP)
- BOOT_5[NAND_D5]: 0= USB Boot First
- BOOT_6[NAND_D6]: 0= SPI NOR Boot First
- * REV1.0
- close to branch ponit
- Only Support SLC NAND Flash
  Not Support MLC NAND Flash
- Use 1.8V power SPI nor Flash if VDDIO_BOOT is 1.8V.
sheet 9
- OUT2A/OUT2B =(-)
- OUT1A/OUT1B=(+)
- RIGHT WOOFER
- Device Address: 0x58
- +
- -
- Woofer
- +
- -
- Full Range
- OUT1A/OUT1B=(+)
- OUT2A/OUT2B =(-)
- * REV1.0
- RIGHT FULL RANGE
- Device Address: 0x5A
sheet 10
- TP -TP: 2.5mm
  Bottom Layer
- OUT2A/OUT2B =(-)
- OUT1A/OUT1B=(+)
- LEFT WOOFER
- +
- Device Address: 0x54
- -
- Woofer
- -
- +
- Full Range
- OUT1A/OUT1B=(+)
- OUT2A/OUT2B =(-)
- * REV1.0
- LEFT FULL RANGE
- Device Address: 0x56
sheet 11
- * REV1.0
- * DVT3
- 1
- 2
- * DVT3
- 13
- 14
- TP -TP: 2.54mm
  Bottom Layer
